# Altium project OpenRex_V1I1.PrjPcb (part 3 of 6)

## Sheet [12] - CPU - POWER.SchDoc
size A2; DocumentNumber: 12; SheetNumber: 12; SheetTotal: 31
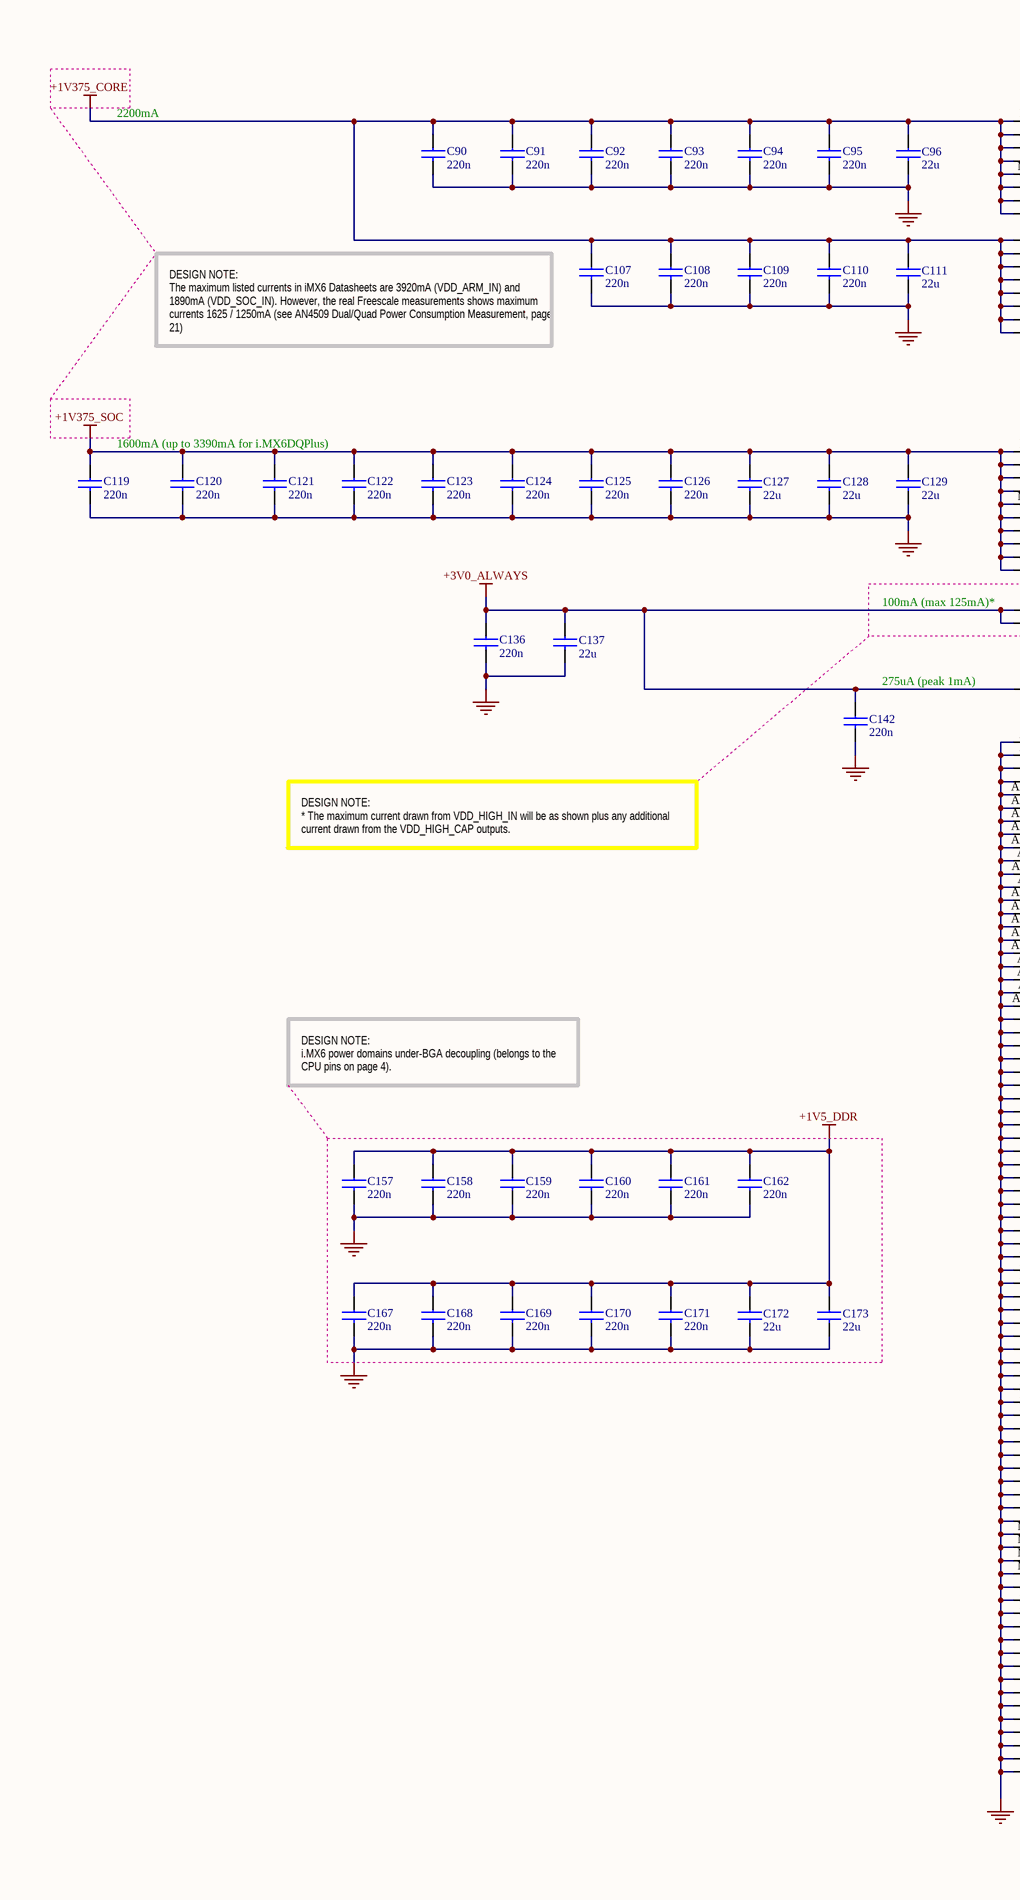
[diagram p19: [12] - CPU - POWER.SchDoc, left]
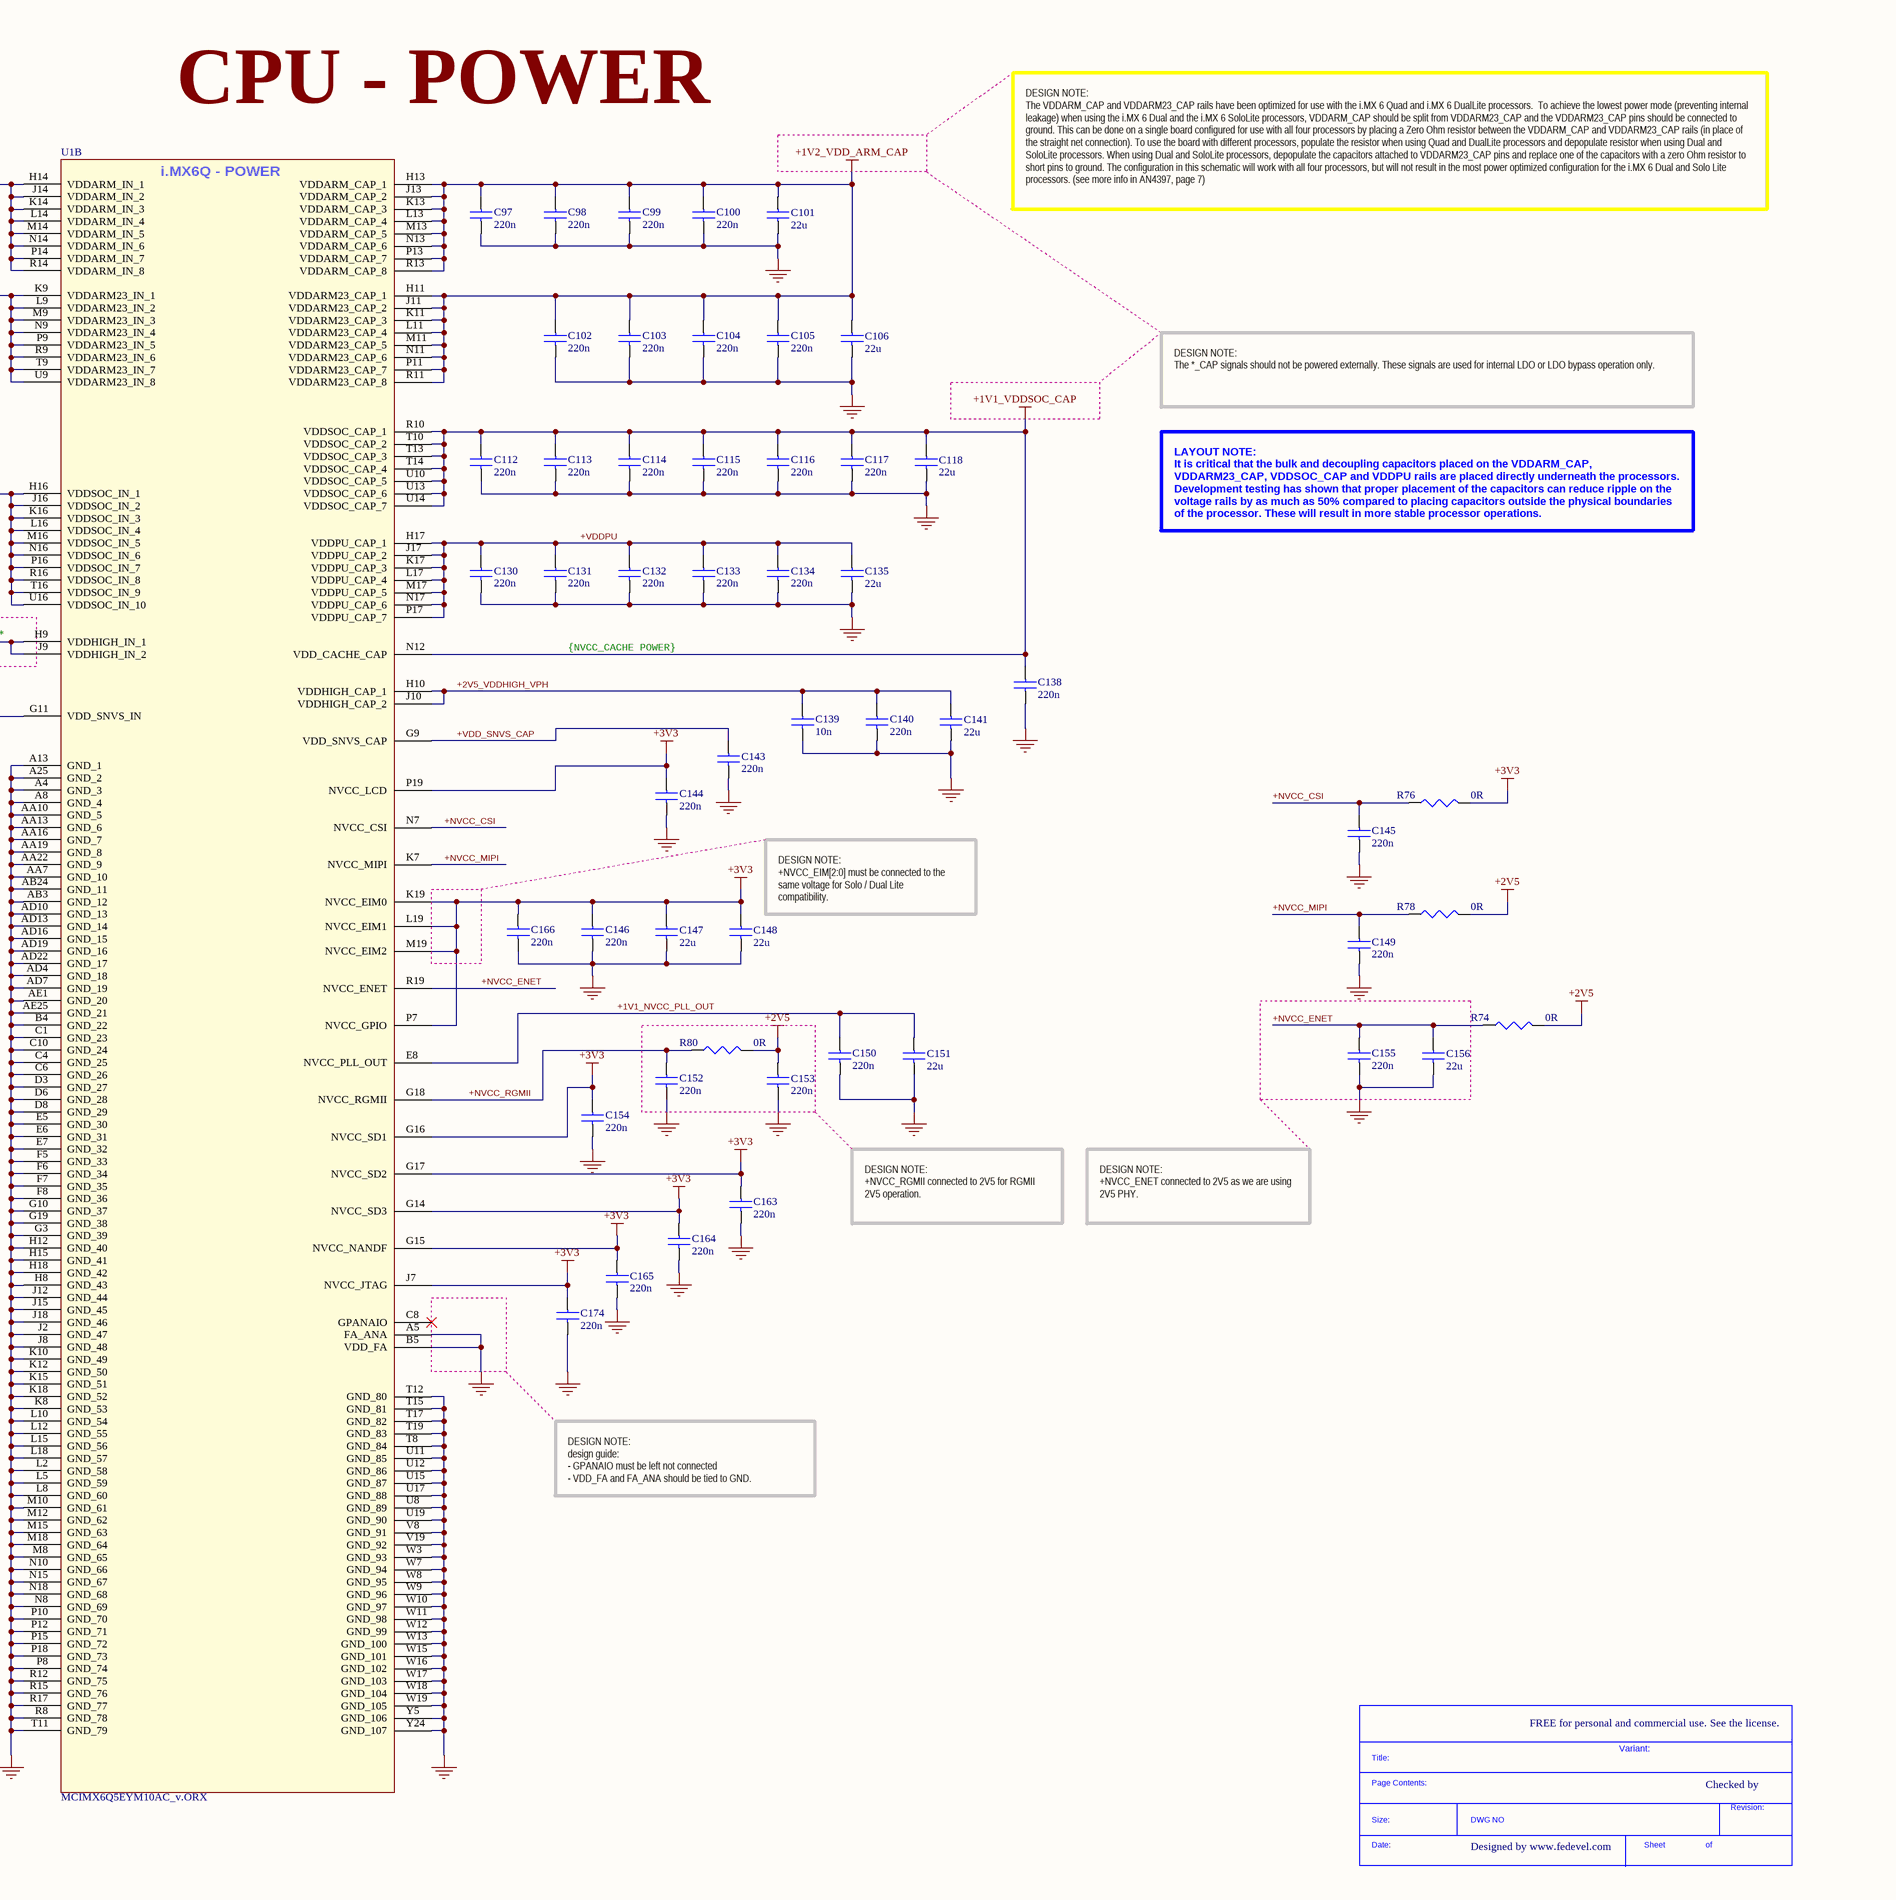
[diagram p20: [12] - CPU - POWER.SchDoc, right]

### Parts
(Parts that share a designator on the sheet are numbered #1, #2 ... from top to bottom, then left to right.)
*#13  SDTitleBlock  (value not drawn)  (graphical)
C90  220n  [C0201]
C91  220n  [C0201]
C92  220n  [C0201]
C93  220n  [C0201]
C94  220n  [C0201]
C95  220n  [C0201]
C96  22u  [C0603_small]
C97  220n  [C0201]
C98  220n  [C0201]
C99  220n  [C0201]
C100  220n  [C0201]
C101  22u  [C0603_small]
C102  220n  [C0201]
C103  220n  [C0201]
C104  220n  [C0201]
C105  220n  [C0201]
C106  22u  [C0603_small]
C107  220n  [C0201]
C108  220n  [C0201]
C109  220n  [C0201]
C110  220n  [C0201]
C111  22u  [C0603_small]
C112  220n  [C0201]
C113  220n  [C0201]
C114  220n  [C0201]
C115  220n  [C0201]
C116  220n  [C0201]
C117  220n  [C0201]
C118  22u  [C0603_small]
C119  220n  [C0201]
C120  220n  [C0201]
C121  220n  [C0201]
C122  220n  [C0201]
C123  220n  [C0201]
C124  220n  [C0201]
C125  220n  [C0201]
C126  220n  [C0201]
C127  22u  [C0603_small]
C128  22u  [C0603_small]
C129  22u  [C0603_small]
C130  220n  [C0201]
C131  220n  [C0201]
C132  220n  [C0201]
C133  220n  [C0201]
C134  220n  [C0201]
C135  22u  [C0603_small]
C136  220n  [C0201]
C137  22u  [C0603]
C138  220n  [C0201]
C139  10n  [C0201]
C140  220n  [C0201]
C141  22u  [C0603]
C142  220n  [C0201]
C143  220n  [C0201]
C144  220n  [C0201]
C145  220n  [C0201]
C146  220n  [C0201]
C147  22u  [C0603]
C148  22u  [C0603]
C149  220n  [C0201]
C150  220n  [C0201]
C151  22u  [C0603]
C152  220n  [C0201]
C153  220n  [C0402]
C154  220n  [C0201]
C155  220n  [C0201]
C156  22u  [C0603]
C157  220n  [C0201]
C158  220n  [C0201]
C159  220n  [C0201]
C160  220n  [C0201]
C161  220n  [C0201]
C162  220n  [C0201]
C163  220n  [C0201]
C164  220n  [C0201]
C165  220n  [C0201]
C166  220n  [C0201]
C167  220n  [C0201]
C168  220n  [C0201]
C169  220n  [C0201]
C170  220n  [C0201]
C171  220n  [C0201]
C172  22u  [C0603_small]
C173  22u  [C0603_small]
C174  220n  [C0201]
R74  0R  [R0402]
R76  0R  [R0402]
R78  0R  [R0402]
R80  0R  [R0402]
U1  MCIMX6Q5EYM10AC_v.ORX  [PBGA624]  (part B of 21)

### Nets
+1V1_VDDSOC_CAP: C112.1 C113.1 C114.1 C115.1 C116.1 C117.1 C118.1 C138.1 U1.N12(VDD_CACHE_CAP) U1.R10(VDDSOC_CAP_1) U1.T10(VDDSOC_CAP_2) U1.T13(VDDSOC_CAP_3) U1.T14(VDDSOC_CAP_4) U1.U10(VDDSOC_CAP_5) U1.U13(VDDSOC_CAP_6) U1.U14(VDDSOC_CAP_7)
+1V2_VDD_ARM_CAP: C97.1 C98.1 C99.1 C100.1 C101.1 C102.1 C103.1 C104.1 C105.1 C106.1 U1.H11(VDDARM23_CAP_1) U1.H13(VDDARM_CAP_1) U1.J11(VDDARM23_CAP_2) U1.J13(VDDARM_CAP_2) U1.K11(VDDARM23_CAP_3) U1.K13(VDDARM_CAP_3) U1.L11(VDDARM23_CAP_4) U1.L13(VDDARM_CAP_4) U1.M11(VDDARM23_CAP_5) U1.M13(VDDARM_CAP_5) U1.N11(VDDARM23_CAP_6) U1.N13(VDDARM_CAP_6) U1.P11(VDDARM23_CAP_7) U1.P13(VDDARM_CAP_7) U1.R11(VDDARM23_CAP_8) U1.R13(VDDARM_CAP_8)
+1V5_DDR: C157.1 C158.1 C159.1 C160.1 C161.1 C162.1 C167.1 C168.1 C169.1 C170.1 C171.1 C172.1 C173.1
+1V375_CORE: C90.1 C91.1 C92.1 C93.1 C94.1 C95.1 C96.1 C107.1 C108.1 C109.1 C110.1 C111.1 U1.H14(VDDARM_IN_1) U1.J14(VDDARM_IN_2) U1.K9(VDDARM23_IN_1) U1.K14(VDDARM_IN_3) U1.L9(VDDARM23_IN_2) U1.L14(VDDARM_IN_4) U1.M9(VDDARM23_IN_3) U1.M14(VDDARM_IN_5) U1.N9(VDDARM23_IN_4) U1.N14(VDDARM_IN_6) U1.P9(VDDARM23_IN_5) U1.P14(VDDARM_IN_7) U1.R9(VDDARM23_IN_6) U1.R14(VDDARM_IN_8) U1.T9(VDDARM23_IN_7) U1.U9(VDDARM23_IN_8)
+1V375_SOC: C119.1 C120.1 C121.1 C122.1 C123.1 C124.1 C125.1 C126.1 C127.1 C128.1 C129.1 U1.H16(VDDSOC_IN_1) U1.J16(VDDSOC_IN_2) U1.K16(VDDSOC_IN_3) U1.L16(VDDSOC_IN_4) U1.M16(VDDSOC_IN_5) U1.N16(VDDSOC_IN_6) U1.P16(VDDSOC_IN_7) U1.R16(VDDSOC_IN_8) U1.T16(VDDSOC_IN_9) U1.U16(VDDSOC_IN_10)
+2V5: C153.1 R74.2 R78.2 R80.2
+3V0_ALWAYS: C136.1 C137.1 C142.1 U1.G11(VDD_SNVS_IN) U1.H9(VDDHIGH_IN_1) U1.J9(VDDHIGH_IN_2)
+3V3: C144.1 C146.1 C147.1 C148.1 C154.1 C163.1 C164.1 C165.1 C166.1 C174.1 R76.2 U1.G14(NVCC_SD3) U1.G15(NVCC_NANDF) U1.G16(NVCC_SD1) U1.G17(NVCC_SD2) U1.J7(NVCC_JTAG) U1.K19(NVCC_EIM0) U1.L19(NVCC_EIM1) U1.M19(NVCC_EIM2) U1.P7(NVCC_GPIO) U1.P19(NVCC_LCD)
GND: C90.2 C91.2 C92.2 C93.2 C94.2 C95.2 C96.2 C97.2 C98.2 C99.2 C100.2 C101.2 C102.2 C103.2 C104.2 C105.2 C106.2 C107.2 C108.2 C109.2 C110.2 C111.2 C112.2 C113.2 C114.2 C115.2 C116.2 C117.2 C118.2 C119.2 C120.2 C121.2 C122.2 C123.2 C124.2 C125.2 C126.2 C127.2 C128.2 C129.2 C130.2 C131.2 C132.2 C133.2 C134.2 C135.2 C136.2 C137.2 C138.2 C139.2 C140.2 C141.2 C142.2 C143.2 C144.2 C145.2 C146.2 C147.2 C148.2 C149.2 C150.2 C151.2 C152.2 C153.2 C154.2 C155.2 C156.2 C157.2 C158.2 C159.2 C160.2 C161.2 C162.2 C163.2 C164.2 C165.2 C166.2 C167.2 C168.2 C169.2 C170.2 C171.2 C172.2 C173.2 C174.2 U1.A4(GND_3) U1.A5(FA_ANA) U1.A8(GND_4) U1.A13(GND_1) U1.A25(GND_2) U1.AA7(GND_10) U1.AA10(GND_5) U1.AA13(GND_6) U1.AA16(GND_7) U1.AA19(GND_8) U1.AA22(GND_9) U1.AB3(GND_12) U1.AB24(GND_11) U1.AD4(GND_18) U1.AD7(GND_19) U1.AD10(GND_13) U1.AD13(GND_14) U1.AD16(GND_15) U1.AD19(GND_16) U1.AD22(GND_17) U1.AE1(GND_20) U1.AE25(GND_21) U1.B4(GND_22) U1.B5(VDD_FA) U1.C1(GND_23) U1.C4(GND_25) U1.C6(GND_26) U1.C10(GND_24) U1.D3(GND_27) U1.D6(GND_28) U1.D8(GND_29) U1.E5(GND_30) U1.E6(GND_31) U1.E7(GND_32) U1.F5(GND_33) U1.F6(GND_34) U1.F7(GND_35) U1.F8(GND_36) U1.G3(GND_39) U1.G10(GND_37) U1.G19(GND_38) U1.H8(GND_43) U1.H12(GND_40) U1.H15(GND_41) U1.H18(GND_42) U1.J2(GND_47) U1.J8(GND_48) U1.J12(GND_44) U1.J15(GND_45) U1.J18(GND_46) U1.K8(GND_53) U1.K10(GND_49) U1.K12(GND_50) U1.K15(GND_51) U1.K18(GND_52) U1.L2(GND_58) U1.L5(GND_59) U1.L8(GND_60) U1.L10(GND_54) U1.L12(GND_55) U1.L15(GND_56) U1.L18(GND_57) U1.M8(GND_65) U1.M10(GND_61) U1.M12(GND_62) U1.M15(GND_63) U1.M18(GND_64) U1.N8(GND_69) U1.N10(GND_66) U1.N15(GND_67) U1.N18(GND_68) U1.P8(GND_74) U1.P10(GND_70) U1.P12(GND_71) U1.P15(GND_72) U1.P18(GND_73) U1.R8(GND_78) U1.R12(GND_75) U1.R15(GND_76) U1.R17(GND_77) U1.T8(GND_84) U1.T11(GND_79) U1.T12(GND_80) U1.T15(GND_81) U1.T17(GND_82) U1.T19(GND_83) U1.U8(GND_89) U1.U11(GND_85) U1.U12(GND_86) U1.U15(GND_87) U1.U17(GND_88) U1.U19(GND_90) U1.V8(GND_91) U1.V19(GND_92) U1.W3(GND_93) U1.W7(GND_94) U1.W8(GND_95) U1.W9(GND_96) U1.W10(GND_97) U1.W11(GND_98) U1.W12(GND_99) U1.W13(GND_100) U1.W15(GND_101) U1.W16(GND_102) U1.W17(GND_103) U1.W18(GND_104) U1.W19(GND_105) U1.Y5(GND_106) U1.Y24(GND_107)
+1V1_NVCC_PLL_OUT: C150.1 C151.1 U1.E8(NVCC_PLL_OUT)
+2V5_VDDHIGH_VPH: C139.1 C140.1 C141.1 U1.H10(VDDHIGH_CAP_1) U1.J10(VDDHIGH_CAP_2)
+NVCC_CSI: C145.1 R76.1 U1.N7(NVCC_CSI)
+NVCC_ENET: C155.1 C156.1 R74.1 U1.R19(NVCC_ENET)
+NVCC_MIPI: C149.1 R78.1 U1.K7(NVCC_MIPI)
+NVCC_RGMII: C152.1 R80.1 U1.G18(NVCC_RGMII)
+VDD_SNVS_CAP: C143.1 U1.G9(VDD_SNVS_CAP)
+VDDPU: C130.1 C131.1 C132.1 C133.1 C134.1 C135.1 U1.H17(VDDPU_CAP_1) U1.J17(VDDPU_CAP_2) U1.K17(VDDPU_CAP_3) U1.L17(VDDPU_CAP_4) U1.M17(VDDPU_CAP_5) U1.N17(VDDPU_CAP_6) U1.P17(VDDPU_CAP_7)

Not connected (* = marked no-connect by the designer): U1 C8(GPANAIO)*

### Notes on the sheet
- CPU - POWER
- 2200mA
- DESIGN NOTE:
  The VDDARM_CAP and VDDARM23_CAP rails have been optimized for use with the i.MX 6 Quad and i.MX 6 DualLite processors.  To achieve the lowest power mode (preventing internal leakage) when using the i.MX 6 Dual and the i.MX 6 SoloLite processors, VDDARM_CAP should be split from VDDARM23_CAP and the VDDARM23_CAP pins should be connected to ground. This can be done on a single board configured for use with all four processors by placing a Zero Ohm resistor between the VDDARM_CAP and VDDARM23_CAP rails (in place of the straight net connection). To use the board with different processors, populate the resistor when using Quad and DualLite processors and depopulate resistor when using Dual and SoloLite processors. When using Dual and SoloLite processors, depopulate the capacitors attached to VDDARM23_CAP pins and replace one of the capacitors with a zero Ohm resistor to short pins to ground. The configuration in this schematic will work with all four processors, but will not result in the most power optimized configuration for the i.MX 6 Dual and Solo Lite processors. (see more info in AN4397, page 7)
- (near C107) DESIGN NOTE:
  The maximum listed currents in iMX6 Datasheets are 3920mA (VDD_ARM_IN) and 1890mA (VDD_SOC_IN). However, the real Freescale measurements shows maximum currents 1625 / 1250mA (see AN4509 Dual/Quad Power Consumption Measurement, page 21)
- DESIGN NOTE:
  The *_CAP signals should not be powered externally. These signals are used for internal LDO or LDO bypass operation only.
- 1600mA (up to 3390mA for i.MX6DQPlus)
- LAYOUT NOTE:
  It is critical that the bulk and decoupling capacitors placed on the VDDARM_CAP, VDDARM23_CAP, VDDSOC_CAP and VDDPU rails are placed directly underneath the processors. Development testing has shown that proper placement of the capacitors can reduce ripple on the voltage rails by as much as 50% compared to placing capacitors outside the physical boundaries of the processor. These will result in more stable processor operations.
- 100mA (max 125mA)*
- {NVCC_CACHE POWER}
- (near C142) 275uA (peak 1mA)
- DESIGN NOTE:
  * The maximum current drawn from VDD_HIGH_IN will be as shown plus any additional current drawn from the VDD_HIGH_CAP outputs.
- (near C148) DESIGN NOTE:
  +NVCC_EIM[2:0] must be connected to the same voltage for Solo / Dual Lite compatibility.
- DESIGN NOTE:
  i.MX6 power domains under-BGA decoupling (belongs to the CPU pins on page 4).
- DESIGN NOTE:
  +NVCC_RGMII connected to 2V5 for RGMII 2V5 operation.
- DESIGN NOTE:
  +NVCC_ENET connected to 2V5 as we are using 2V5 PHY.
- DESIGN NOTE:
  design guide:
  - GPANAIO must be left not connected
  - VDD_FA and FA_ANA should be tied to GND.
- FREE for personal and commercial use. See the license.
- Variant:
- Checked by
- Designed by www.fedevel.com

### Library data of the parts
C90-C95 C97-C100 C102-C105 C107-C110 C112-C117 C119-C126 C130-C134 C136 C138 C140 C142-C146 C149 C150 C152 C154 C155 C157-C171 C174 = C0603X5R0J224M030BB: CAP CER 0.22UF 6.3V 20% X5R 0201; Manufacturer: TDK Corporation; Capacitance: 0.22µF; .Checked PCB: MM
C96 C101 C106 C111 C118 C127-C129 C135 C172 C173 = GRM188R60G226MEA0L_small: CAP CER 22UF 4V 20% X5R 0603; Manufacturer: Murata Electronics North America; Capacitance: 22µF; .Checked PCB: MM; .Checked SCH: RF, used by MM
C137 C141 C147 C148 C151 C156 = C1608X5R0J226M080AC: CAP CER 22UF 6.3V 20% X5R 0603; Manufacturer: TDK Corporation; Capacitance: 22µF; .Creator: MM
C139 = C0603X5R1C103K030BA: CAP CER .01UF 16V 10% X5R 0201; Manufacturer: TDK Corporation; Capacitance: 10000pF; .Creator: MM
C153 = C1005X5R1E224M: CAP CER .22UF 25V X5R 20% 0402; Manufacturer: TDK Corporation; Capacitance: 0.22µF; Value: 220nF; .Checked PCB: used
R74 R76 R78 R80 = RC0402JR-070RL: RES 0.0 OHM 1/16W 0402 SMD; Manufacturer: Yageo; Resistance (Ohms): 0.0; Power (Watts): 0.063W, 1/16W; Tolerance: Jumper; .Checked PCB: used
U1 = MCIMX6Q5EYM10AC_v.ORX: IC MCU 32BIT ARM QUAD 624FCBGA; Manufacturer: Freescale Semiconductor; Core Processor: ARM® Cortex™-A9; Core Size: 32-Bit Quad-Core; Speed: 1.0GHz; Connectivity: CAN, EBI/EMI, ESAI, Ethernet, GPMI, I2C, MMC/SD, PCI, SATA, SPI, UART, USB, USB OTG; Peripherals: DMA, HDMI, I2S/SSI/AC97, MIPI CSI, MIMI DSI, MIPI HIS, PWM, WDT; Number of I /O: 224; Program Memory Type: External Program Memory; RAM Size: 256K x 8; Voltage - Supply (Vcc/Vdd): 0.925 V ~ 1.5 V; Oscillator Type: Internal; .Creator: MM; .Checked PCB: MM, checked by RF

## Sheet [18] - PCIE MINI.SchDoc
size A2; DocumentNumber: 18; SheetNumber: 18; SheetTotal: 31
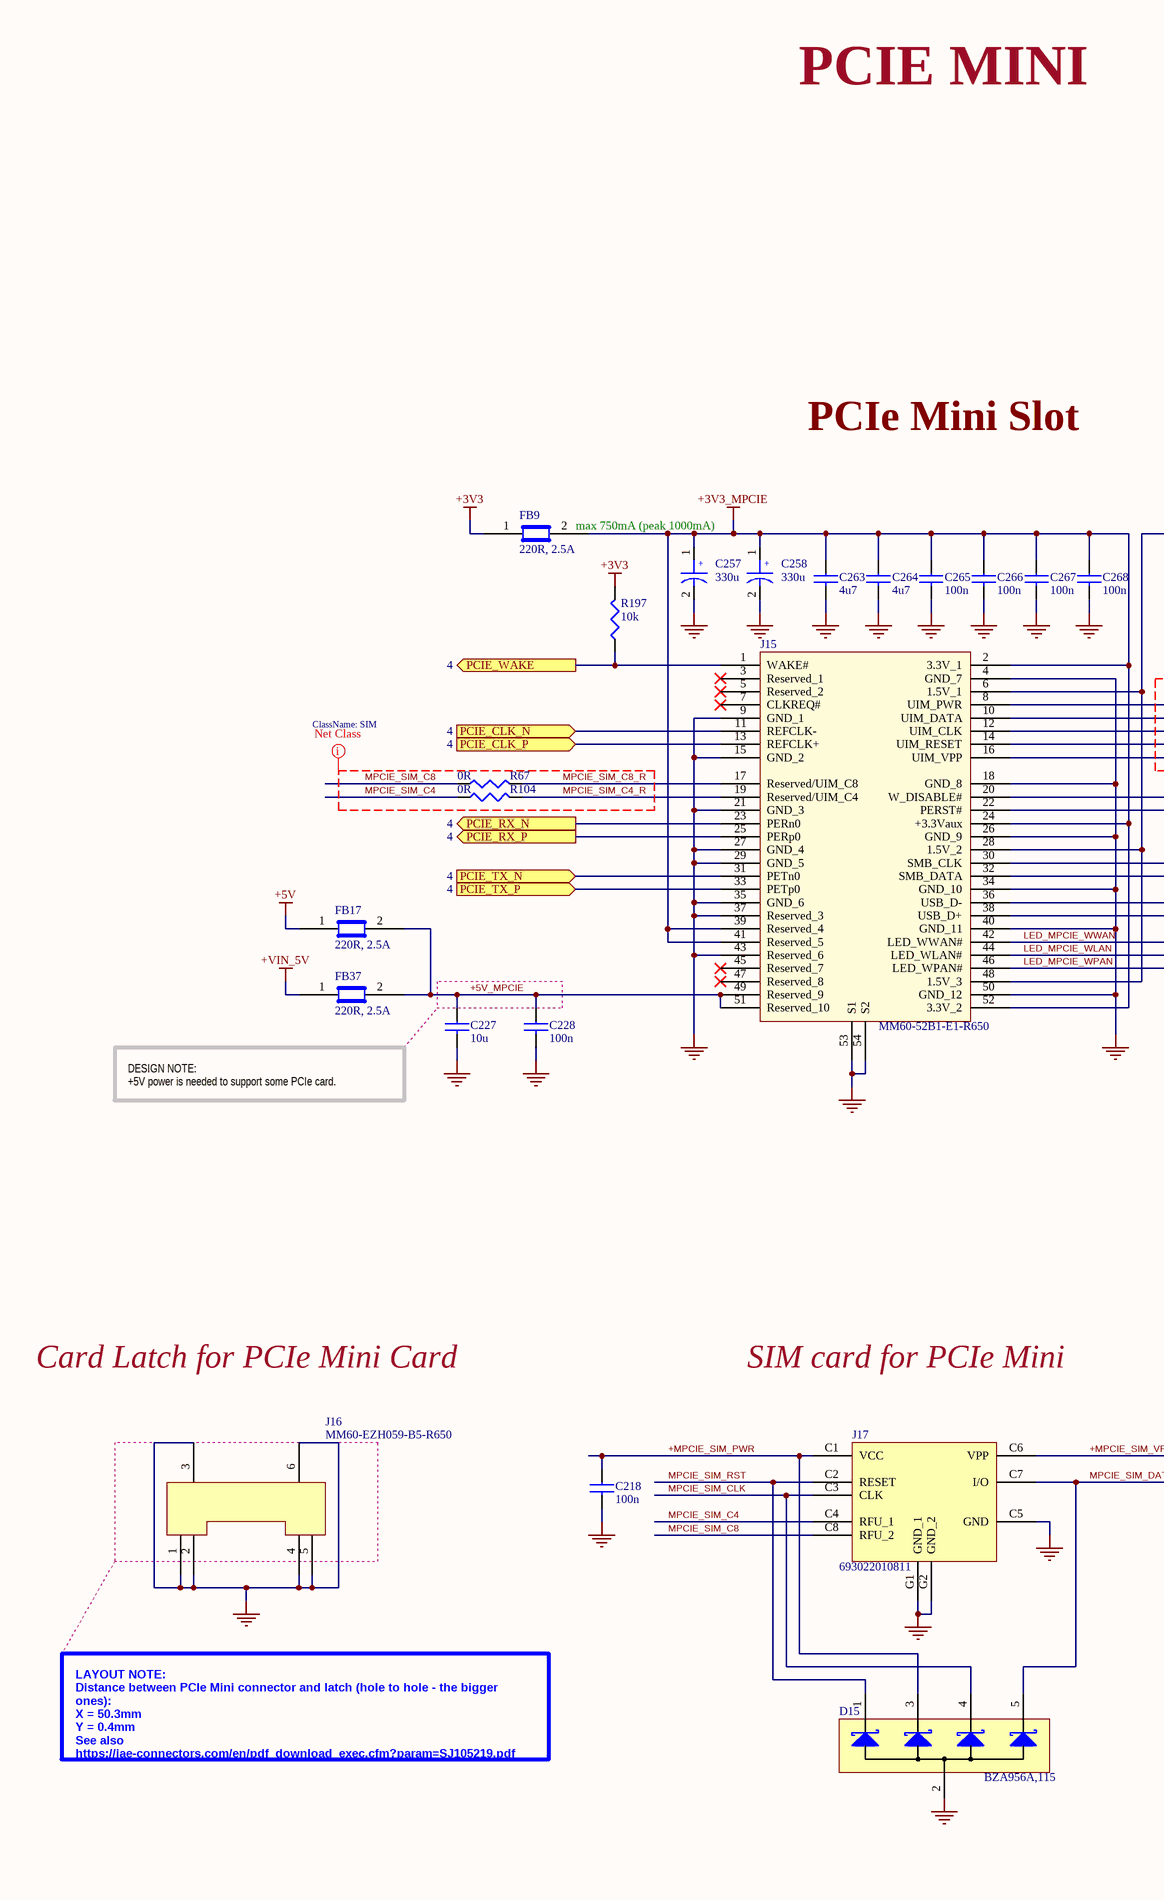
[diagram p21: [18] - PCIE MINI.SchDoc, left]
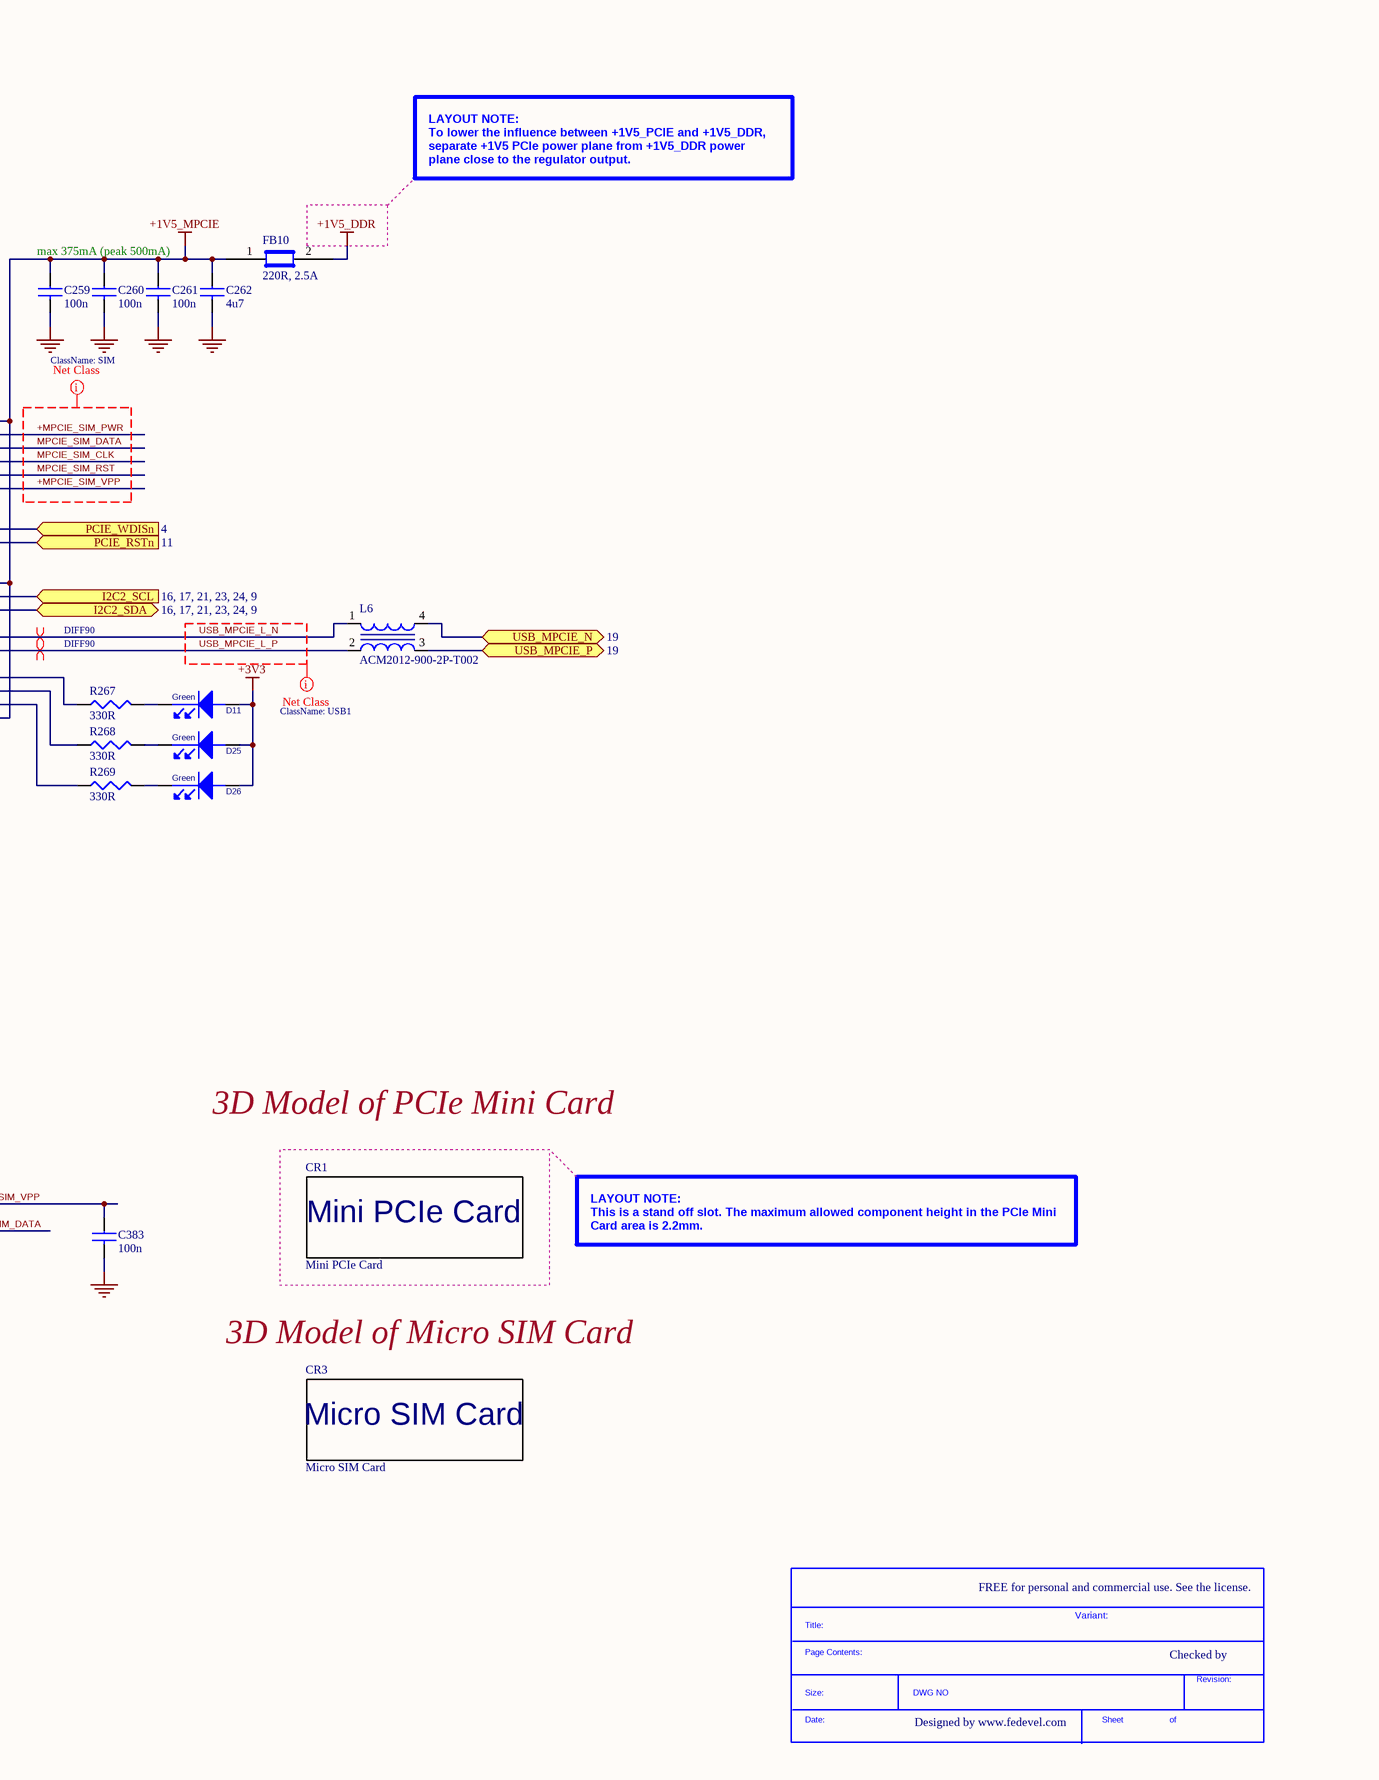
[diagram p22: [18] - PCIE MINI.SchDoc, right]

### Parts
(Parts that share a designator on the sheet are numbered #1, #2 ... from top to bottom, then left to right.)
*#14  SDTitleBlock  (value not drawn)  (graphical)
C218  100n  [C0402]
C227  10u  [C0603]
C228  100n  [C0402]
C257  330u  [C2917]
C258  330u  [C2917]
C259  100n  [C0402]
C260  100n  [C0402]
C261  100n  [C0402]
C262  4u7  [C0402]
C263  4u7  [C0402]
C264  4u7  [C0402]
C265  100n  [C0402]
C266  100n  [C0402]
C267  100n  [C0402]
C268  100n  [C0402]
C383  100n  [C0402]
CR1  Mini PCIe Card  [Mini_PCIe_full card]  (no BOM)
CR3  Micro SIM Card  [Micro_Sim_card]  (no BOM)
D11  Green  [LED_0603]
D15  BZA956A,115  [SOT665]
D25  Green  [LED_0603]
D26  Green  [LED_0603]
FB9  220R, 2.5A  [C0603]
FB10  220R, 2.5A  [C0603]
FB17  220R, 2.5A  [C0603]
FB37  220R, 2.5A  [C0603]
J15  MM60-52B1-E1-R650  [MINI_PCIE_52PIN_CARD_CON]
J16  MM60-EZH059-B5-R650  [MINI_PCIE_52PIN_CARD_LATCH]
J17  693022010811  [SIM_MICRO_HINGED]
L6  ACM2012-900-2P-T002  [ACM2012]
R67  0R  [R0402]
R104  0R  [R0402]
R197  10k  [R0402]
R267  330R  [R0402]
R268  330R  [R0402]
R269  330R  [R0402]

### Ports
I2C2_SCL (see 16, 17, 21, 23, 24, 9), I2C2_SDA (bidir, see 16, 17, 21, 23, 24, 9), PCIE_CLK_N (in, see 4), PCIE_CLK_P (in, see 4), PCIE_RSTn (in, see 11), PCIE_RX_N (out, see 4), PCIE_RX_P (out, see 4), PCIE_TX_N (in, see 4), PCIE_TX_P (in, see 4), PCIE_WAKE (out, see 4), PCIE_WDISn (in, see 4), USB_MPCIE_N (bidir, see 19), USB_MPCIE_P (bidir, see 19)

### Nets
+1V5_DDR: FB10.2
+1V5_MPCIE: C259.1 C260.1 C261.1 C262.1 FB10.1 J15.6(1.5V_1) J15.28(1.5V_2) J15.48(1.5V_3)
+3V3: D11.2(ANODE) D25.2(ANODE) D26.2(ANODE) FB9.1 R197.2
+3V3_MPCIE: C257.1 C258.1 C263.1 C264.1 C265.1 C266.1 C267.1 C268.1 FB9.2 J15.2(3.3V_1) J15.24(+3.3Vaux) J15.39(Reserved_4) J15.41(Reserved_5) J15.52(3.3V_2)
+5V: FB17.1
+VIN_5V: FB37.1
GND: C218.2 C227.2 C228.2 C257.2 C258.2 C259.2 C260.2 C261.2 C262.2 C263.2 C264.2 C265.2 C266.2 C267.2 C268.2 C383.2 D15.2 J15.4(GND_7) J15.9(GND_1) J15.15(GND_2) J15.18(GND_8) J15.21(GND_3) J15.26(GND_9) J15.27(GND_4) J15.29(GND_5) J15.34(GND_10) J15.35(GND_6) J15.37(Reserved_3) J15.40(GND_11) J15.43(Reserved_6) J15.50(GND_12) J15.53(S1) J15.54(S2) J16.1 J16.2 J16.3 J16.4 J16.5 J16.6 J17.C5(GND) J17.G1(GND_1) J17.G2(GND_2)
+5V_MPCIE: C227.1 C228.1 FB17.2 FB37.2 J15.49(Reserved_9) J15.51(Reserved_10)
+MPCIE_SIM_PWR: C218.1 D15.3 J15.8(UIM_PWR) J17.C1(VCC)
+MPCIE_SIM_VPP: C383.1 J15.16(UIM_VPP) J17.C6(VPP)
I2C2_SCL: J15.30(SMB_CLK) ; port I2C2_SCL
I2C2_SDA: J15.32(SMB_DATA) ; port I2C2_SDA
LED_MPCIE_WLAN: J15.44(LED_WLAN#) R268.1
LED_MPCIE_WPAN: J15.46(LED_WPAN#) R269.1
LED_MPCIE_WWAN: J15.42(LED_WWAN#) R267.1
MPCIE_SIM_C4: J17.C4(RFU_1) R104.1
MPCIE_SIM_C4_R: J15.19(Reserved/UIM_C4) R104.2
MPCIE_SIM_C8: J17.C8(RFU_2) R67.1
MPCIE_SIM_C8_R: J15.17(Reserved/UIM_C8) R67.2
MPCIE_SIM_CLK: D15.4 J15.12(UIM_CLK) J17.C3(CLK)
MPCIE_SIM_DATA: D15.5 J15.10(UIM_DATA) J17.C7(I/O)
MPCIE_SIM_RST: D15.1 J15.14(UIM_RESET) J17.C2(RESET)
PCIE_CLK_N: J15.11(REFCLK-) ; port PCIE_CLK_N
PCIE_CLK_P: J15.13(REFCLK+) ; port PCIE_CLK_P
PCIE_RSTn: J15.22(PERST#) ; port PCIE_RSTn
PCIE_RX_N: J15.23(PERn0) ; port PCIE_RX_N
PCIE_RX_P: J15.25(PERp0) ; port PCIE_RX_P
PCIE_TX_N: J15.31(PETn0) ; port PCIE_TX_N
PCIE_TX_P: J15.33(PETp0) ; port PCIE_TX_P
PCIE_WAKE: J15.1(WAKE#) R197.1 ; port PCIE_WAKE
PCIE_WDISn: J15.20(W_DISABLE#) ; port PCIE_WDISn
USB_MPCIE_L_N: J15.36(USB_D-) L6.1
USB_MPCIE_L_P: J15.38(USB_D+) L6.2
USB_MPCIE_N: L6.4 ; port USB_MPCIE_N
USB_MPCIE_P: L6.3 ; port USB_MPCIE_P
NetD11_1: D11.1(cathode) R267.2
NetD25_1: D25.1(cathode) R268.2
NetD26_1: D26.1(cathode) R269.2

Not connected (* = marked no-connect by the designer): J15 3(Reserved_1)* 5(Reserved_2)* 7(CLKREQ#)* 45(Reserved_7)* 47(Reserved_8)*

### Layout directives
differential pair; net class DIFF90: USB_MPCIE_L_N, USB_MPCIE_L_P
net class USB1: USB_MPCIE_L_N, USB_MPCIE_L_P
net class SIM: +MPCIE_SIM_PWR, +MPCIE_SIM_VPP, MPCIE_SIM_C4, MPCIE_SIM_C4_R, MPCIE_SIM_C8, MPCIE_SIM_C8_R, MPCIE_SIM_CLK, MPCIE_SIM_DATA, MPCIE_SIM_RST

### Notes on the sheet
- PCIE MINI
- PCIe Mini Slot
- LAYOUT NOTE:
  To lower the influence between +1V5_PCIE and +1V5_DDR, separate +1V5 PCIe power plane from +1V5_DDR power plane close to the regulator output.
- max 750mA (peak 1000mA)
- max 375mA (peak 500mA)
- DESIGN NOTE:
  +5V power is needed to support some PCIe card.
- Card Latch for PCIe Mini Card
- SIM card for PCIe Mini
- 3D Model of PCIe Mini Card
- LAYOUT NOTE:
  This is a stand off slot. The maximum allowed component height in the PCIe Mini Card area is 2.2mm.
- 3D Model of Micro SIM Card
- LAYOUT NOTE:
  Distance between PCIe Mini connector and latch (hole to hole - the bigger ones):
  X = 50.3mm
  Y = 0.4mm
  See also https://jae-connectors.com/en/pdf_download_exec.cfm?param=SJ105219.pdf
- FREE for personal and commercial use. See the license.
- Variant:
- Checked by
- Designed by www.fedevel.com

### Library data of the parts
C218 C228 C259-C261 C265-C268 C383 = C1005X5R1H104K: CAP CER .10UF 50V X5R 10% 0402; Manufacturer: TDK Corporation; Capacitance: 0.1µF; Value: 100nF; .Checked PCB: used
C227 = C1608X5R0J106M: CAP CER 10UF 6.3V X5R 20% 0603; Manufacturer: TDK Corporation; Capacitance: 10µF; Value: 10µF; .Checked PCB: used
C257 C258 = T520D337M006ATE045: CAP TANT 330UF 6.3V 20% 2917; Manufacturer: Kemet; Manufacturer Size Code: D; Capacitance: 330µF; ESR (Equivalent Series Resistance): 45 mOhm; Type: Molded; .Creator: MM; .Checked PCB: used
C262-C264 = C1005X5R1A475M: CAP CER 4.7UF 10V 20% X5R 0402; Manufacturer: TDK Corporation; Capacitance: 4.7µF; .Checked PCB: used
CR1 = Card_Mini_PCIe: Card MIni PCIe; .Creator: MM
CR3 = Card_Micro_SIM: Card Micro SIM; .Creator: MM
D11 D25 D26 = LG L29K-G2J1-24-Z: LED SMARTLED GREEN 570NM 0603; Manufacturer: OSRAM Opto Semiconductors Inc; .Checked PCB: used; Current - Test: 2mA; Voltage - Forward (Vf) Typ: 1.7V; Luminous Flux @ Current - Test: 12 mlm; Millicandela Rating: 3.92mcd; Wavelength - Peak: 572nm; Lens Type: Diffused; Lens Style/Size: Rectangle with Flat Top, 1.3mm x 0.8mm; Viewing Angle: 160°; Regulator Topology: Positive Fixed; Voltage - Output: 2.5V; Voltage - Input: 2.6 V ~ 6 V; Voltage - Dropout (Typical): 0.16V @ 500mA; Number of Regulators: 1; Current - Output: 500mA; Current - Limit (Min): 600mA
D15 = BZA956A,115: TVS ZENER QUAD 5.6V SOT665; Manufacturer: NXP Semiconductors; Voltage - Reverse Standoff (Typ): 3V; Voltage - Breakdown: 5.32V; Power (Watts): 16W; Polarization: 4 Channel Array - Unidirectional; .Creator: MM; .Checked PCB: used
FB9 FB10 FB17 FB37 = BLM18SG221TN1D: FERRITE CHIP 220 OHM 2500MA 0603; Manufacturer: Murata Electronics North America; Impedance @ Frequency: 220 Ohm @ 100MHz; DC Resistance (DCR): 40 mOhm Max; Filter Type: Differential Mode - Single; Number of Lines: 1; .Checked PCB: used
J15 = MM60-52B1-E1-R650: CONN MINI EXPRESS CARD 52POS SMD; Manufacturer: JAE Electronics; Card Type: PCI Express Mini Card; Gender: Female; Number of Positions: 52; Card Thickness: 0.039" (1.00mm); Pitch: 0.031" (0.80mm); Material - Insulation: Thermoplastic; Read Out: Dual; .Creator: MM; .Checked PCB: used
J16 = MM60-EZH059-B5-R650: CONN MINI EXPRESS CARD LATCH SMD; Manufacturer: JAE Electronics; For Use With/Related Products: PCI Express Mini Card; .Creator: MM; .Checked PCB: used
J17 = 693022010811: CONN SMART CARD; Manufacturer: Wurth Electronics Inc; Card Type: Micro SIM; Number of Positions: 8; Connector Type: Connector and Ejector; Insertion, Removal Method: Hinged Lid; .Creator: MM
L6 = ACM2012-900-2P-T002: CHOKE COMM MODE 90 OHM .4A SMD; Manufacturer: TDK Corporation; Filter Type: Data, Signal Line; Number of Lines: 2; Current: 400mA; DC Resistance (DCR): 190 mOhm Max; Impedance: 90 Ohm; Resistance (Ohms): 8.2K; Power (Watts): 0.063W, 1/16W; Temperature Coefficient: ±100ppm/°C; Tolerance: ±1%; .Checked PCB: used
R67 R104 = RC0402JR-070RL: as R74 on sheet [12] - CPU - POWER
R197 = RC0402FR-0710KL: RES 10.0K OHM 1/16W 1% 0402 SMD; Manufacturer: Yageo; Power (Watts): 0.063W, 1/16W; .Checked PCB: used; Temperature Coefficient: ±100ppm/°C
R267-R269 = CRCW0402330RFKED: RES 330 OHM 1/16W 1% 0402 SMD; Manufacturer: Vishay Dale; Resistance (Ohms): 330; Power (Watts): 0.063W, 1/16W; Temperature Coefficient: ±100ppm/°C; .Checked PCB: used

## Sheet [13] - CPU - UNUSED.SchDoc
size A2; DocumentNumber: 13; SheetNumber: 13; SheetTotal: 31
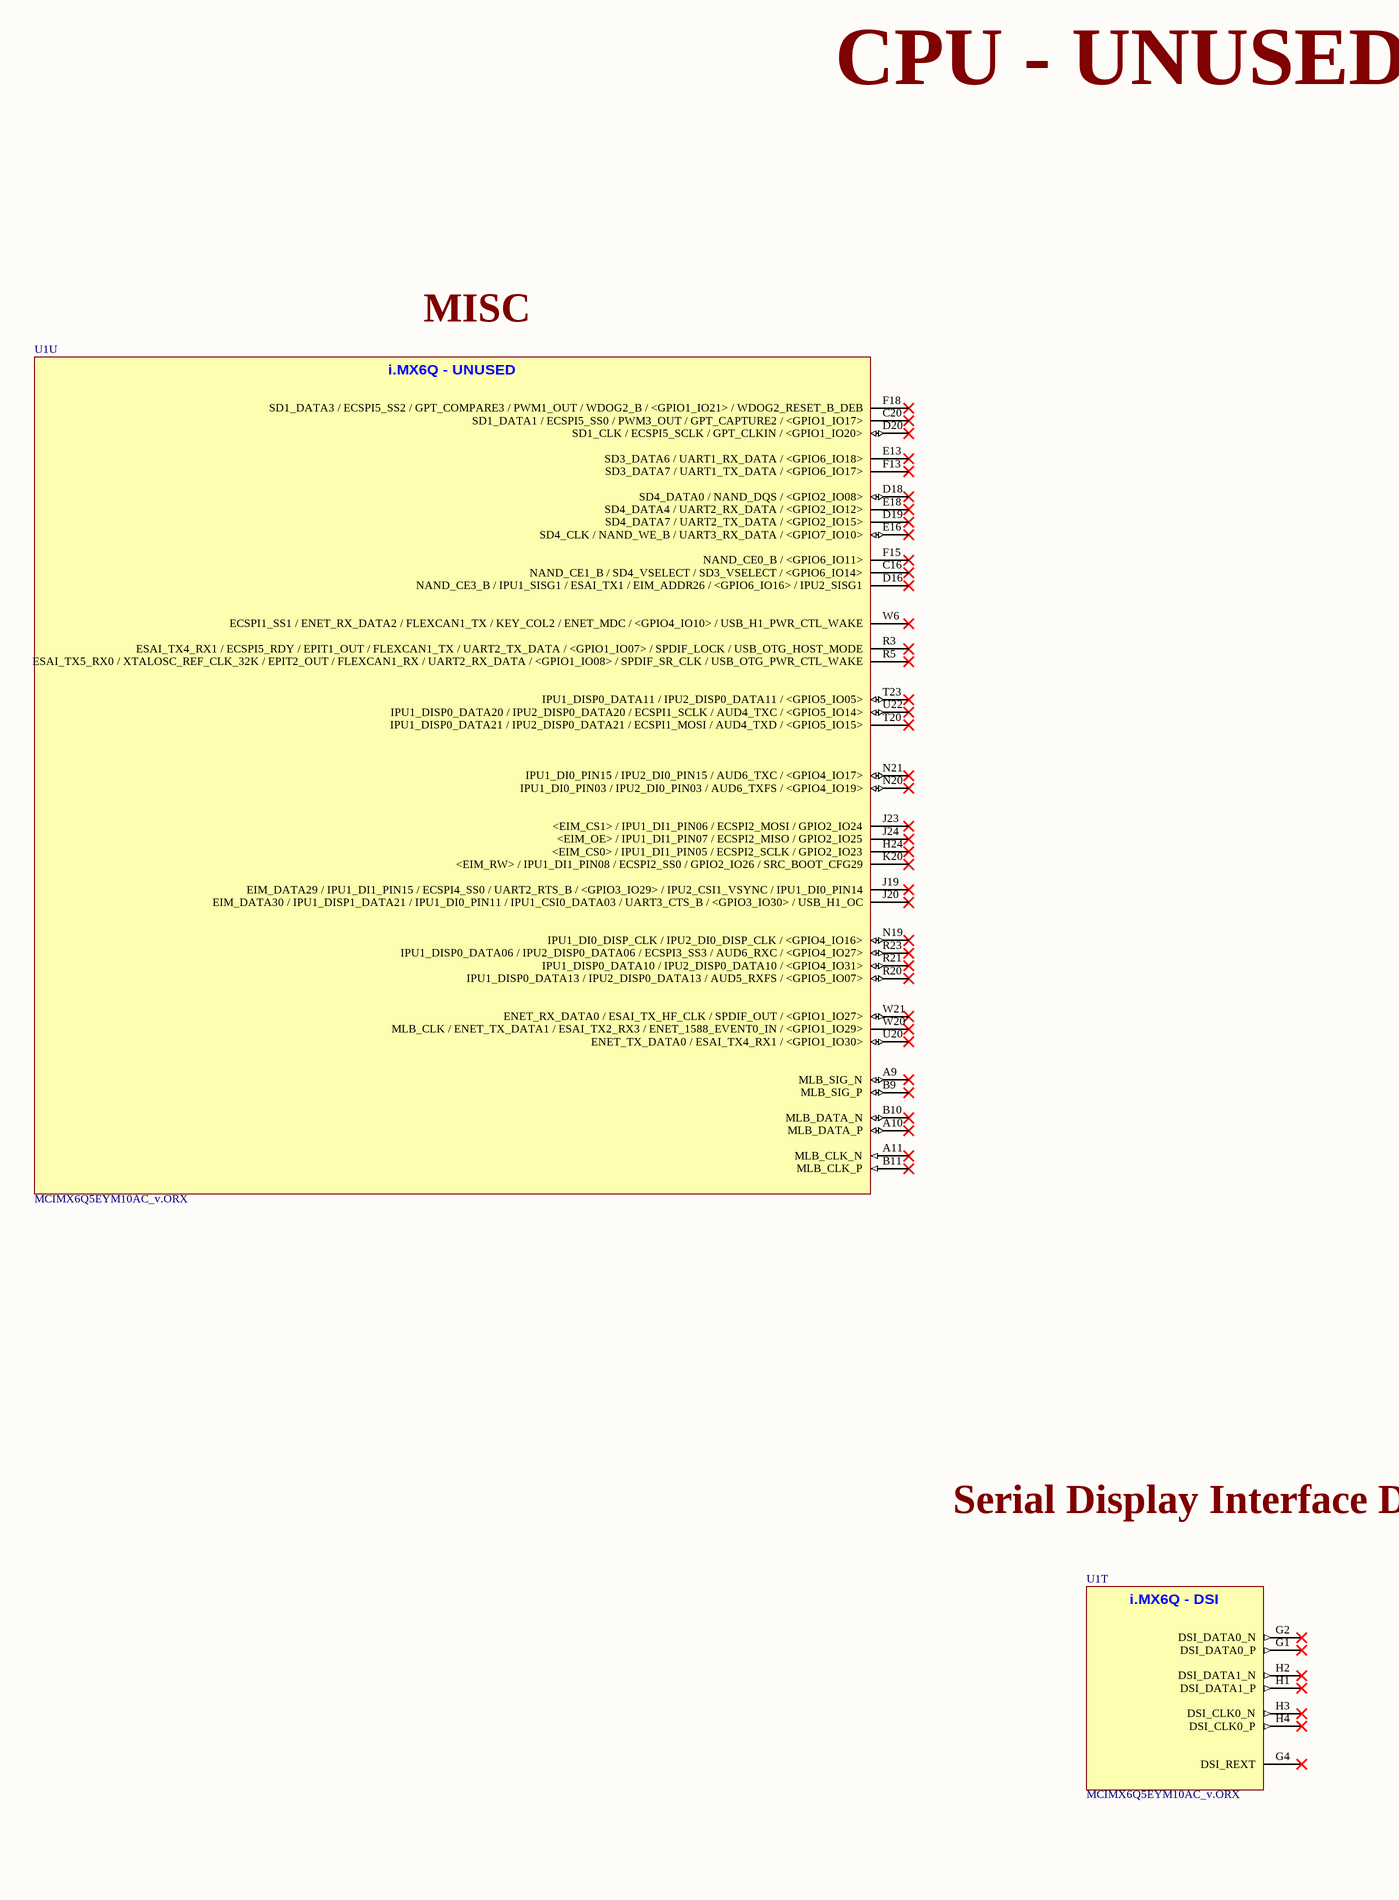
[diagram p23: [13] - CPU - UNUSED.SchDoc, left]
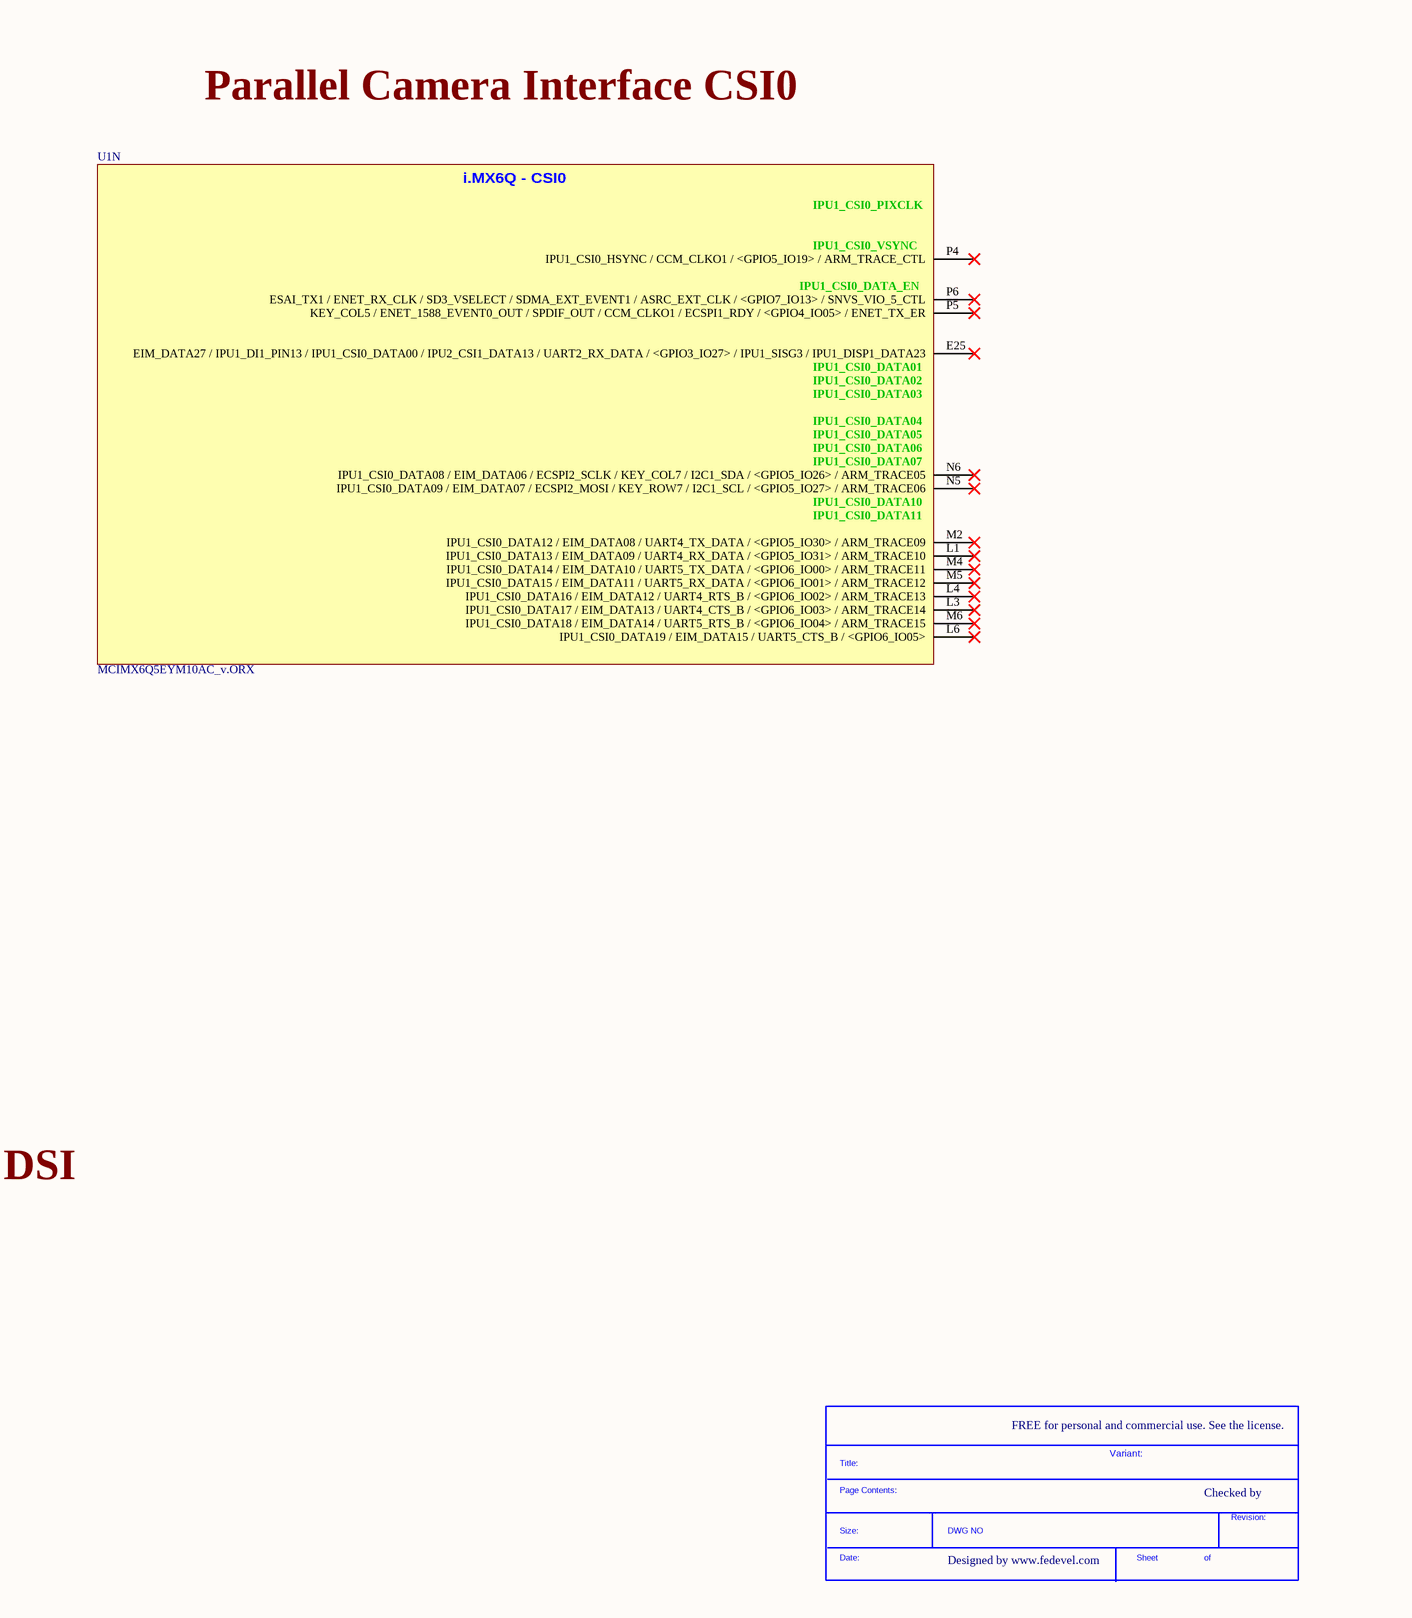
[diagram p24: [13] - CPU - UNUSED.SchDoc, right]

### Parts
(Parts that share a designator on the sheet are numbered #1, #2 ... from top to bottom, then left to right.)
*#15  SDTitleBlock  (value not drawn)  (graphical)
U1  MCIMX6Q5EYM10AC_v.ORX  [PBGA624]  (parts N,T,U of 21)

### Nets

Not connected (* = marked no-connect by the designer): U1 A9(MLB_SIG_N)* A10(MLB_DATA_P)* A11(MLB_CLK_N)* B9(MLB_SIG_P)* B10(MLB_DATA_N)* B11(MLB_CLK_P)* C16(NAND_CE1_B_/_SD4_VSELECT_/_SD3_VSELECT_/_<GPIO6_IO14>)* C20(SD1_DATA1_/_ECSPI5_SS0_/_PWM3_OUT_/_GPT_CAPTURE2_/_<GPIO1_IO17>)* D16(NAND_CE3_B_/_IPU1_SISG1_/_ESAI_TX1_/_EIM_ADDR26_/_<GPIO6_IO16>_/_IPU2_SISG1)* D18(SD4_DATA0_/_NAND_DQS_/_<GPIO2_IO08>)* D19(SD4_DATA7_/_UART2_TX_DATA_/_<GPIO2_IO15>)* D20(SD1_CLK_/_ECSPI5_SCLK_/_GPT_CLKIN_/_<GPIO1_IO20>)* E13(SD3_DATA6_/_UART1_RX_DATA_/_<GPIO6_IO18>)* E16(SD4_CLK_/_NAND_WE_B_/_UART3_RX_DATA_/_<GPIO7_IO10>)* E18(SD4_DATA4_/_UART2_RX_DATA_/_<GPIO2_IO12>)* E25(EIM_DATA27_/_IPU1_DI1_PIN13_/_IPU1_CSI0_DATA00_/_IPU2_CSI1_DATA13_/_UART2_RX_DATA_/_<GPIO3_IO27>_/_IPU1_SISG3_/_IPU1_DISP1_DATA23)* F13(SD3_DATA7_/_UART1_TX_DATA_/_<GPIO6_IO17>)* F15(NAND_CE0_B_/_<GPIO6_IO11>)* F18(SD1_DATA3_/_ECSPI5_SS2_/_GPT_COMPARE3_/_PWM1_OUT_/_WDOG2_B_/_<GPIO1_IO21>_/_WDOG2_RESET_B_DEB)* G1(DSI_DATA0_P)* G2(DSI_DATA0_N)* G4(DSI_REXT)* H1(DSI_DATA1_P)* H2(DSI_DATA1_N)* H3(DSI_CLK0_N)* H4(DSI_CLK0_P)* H24(<EIM_CS0>_/_IPU1_DI1_PIN05_/_ECSPI2_SCLK_/_GPIO2_IO23)* J19(EIM_DATA29_/_IPU1_DI1_PIN15_/_ECSPI4_SS0_/_UART2_RTS_B_/_<GPIO3_IO29>_/_IPU2_CSI1_VSYNC_/_IPU1_DI0_PIN14)* J20(EIM_DATA30_/_IPU1_DISP1_DATA21_/_IPU1_DI0_PIN11_/_IPU1_CSI0_DATA03_/_UART3_CTS_B_/_<GPIO3_IO30>_/_USB_H1_OC)* J23(<EIM_CS1>_/_IPU1_DI1_PIN06_/_ECSPI2_MOSI_/_GPIO2_IO24)* J24(<EIM_OE>_/_IPU1_DI1_PIN07_/_ECSPI2_MISO_/_GPIO2_IO25)* K20(<EIM_RW>_/_IPU1_DI1_PIN08_/_ECSPI2_SS0_/_GPIO2_IO26_/_SRC_BOOT_CFG29)* L1(IPU1_CSI0_DATA13_/_EIM_DATA09_/_UART4_RX_DATA_/_<GPIO5_IO31>_/_ARM_TRACE10)* L3(IPU1_CSI0_DATA17_/_EIM_DATA13_/_UART4_CTS_B_/_<GPIO6_IO03>_/_ARM_TRACE14)* L4(IPU1_CSI0_DATA16_/_EIM_DATA12_/_UART4_RTS_B_/_<GPIO6_IO02>_/_ARM_TRACE13)* L6(IPU1_CSI0_DATA19_/_EIM_DATA15_/_UART5_CTS_B_/_<GPIO6_IO05>)* M2(IPU1_CSI0_DATA12_/_EIM_DATA08_/_UART4_TX_DATA_/_<GPIO5_IO30>_/_ARM_TRACE09)* M4(IPU1_CSI0_DATA14_/_EIM_DATA10_/_UART5_TX_DATA_/_<GPIO6_IO00>_/_ARM_TRACE11)* M5(IPU1_CSI0_DATA15_/_EIM_DATA11_/_UART5_RX_DATA_/_<GPIO6_IO01>_/_ARM_TRACE12)* M6(IPU1_CSI0_DATA18_/_EIM_DATA14_/_UART5_RTS_B_/_<GPIO6_IO04>_/_ARM_TRACE15)* N5(IPU1_CSI0_DATA09_/_EIM_DATA07_/_ECSPI2_MOSI_/_KEY_ROW7_/_I2C1_SCL_/_<GPIO5_IO27>_/_ARM_TRACE06)* N6(IPU1_CSI0_DATA08_/_EIM_DATA06_/_ECSPI2_SCLK_/_KEY_COL7_/_I2C1_SDA_/_<GPIO5_IO26>_/_ARM_TRACE05)* N19(IPU1_DI0_DISP_CLK_/_IPU2_DI0_DISP_CLK_/_<GPIO4_IO16>)* N20(IPU1_DI0_PIN03_/_IPU2_DI0_PIN03_/_AUD6_TXFS_/_<GPIO4_IO19>)* N21(IPU1_DI0_PIN15_/_IPU2_DI0_PIN15_/_AUD6_TXC_/_<GPIO4_IO17>)* P4(IPU1_CSI0_HSYNC_/_CCM_CLKO1_/_<GPIO5_IO19>_/_ARM_TRACE_CTL)* P5(KEY_COL5_/_ENET_1588_EVENT0_OUT_/_SPDIF_OUT_/_CCM_CLKO1_/_ECSPI1_RDY_/_<GPIO4_IO05>_/_ENET_TX_ER)* P6(ESAI_TX1_/_ENET_RX_CLK_/_SD3_VSELECT_/_SDMA_EXT_EVENT1_/_ASRC_EXT_CLK_/_<GPIO7_IO13>_/_SNVS_VIO_5_CTL)* R3(ESAI_TX4_RX1_/_ECSPI5_RDY_/_EPIT1_OUT_/_FLEXCAN1_TX_/_UART2_TX_DATA_/_<GPIO1_IO07>_/_SPDIF_LOCK_/_USB_OTG_HOST_MODE)* R5(ESAI_TX5_RX0_/_XTALOSC_REF_CLK_32K_/_EPIT2_OUT_/_FLEXCAN1_RX_/_UART2_RX_DATA_/_<GPIO1_IO08>_/_SPDIF_SR_CLK_/_USB_OTG_PWR_CTL_WAKE)* R20(IPU1_DISP0_DATA13_/_IPU2_DISP0_DATA13_/_AUD5_RXFS_/_<GPIO5_IO07>)* R21(IPU1_DISP0_DATA10_/_IPU2_DISP0_DATA10_/_<GPIO4_IO31>)* R23(IPU1_DISP0_DATA06_/_IPU2_DISP0_DATA06_/_ECSPI3_SS3_/_AUD6_RXC_/_<GPIO4_IO27>)* T20(IPU1_DISP0_DATA21_/_IPU2_DISP0_DATA21_/_ECSPI1_MOSI_/_AUD4_TXD_/_<GPIO5_IO15>)* T23(IPU1_DISP0_DATA11_/_IPU2_DISP0_DATA11_/_<GPIO5_IO05>)* U20(ENET_TX_DATA0_/_ESAI_TX4_RX1_/_<GPIO1_IO30>)* U22(IPU1_DISP0_DATA20_/_IPU2_DISP0_DATA20_/_ECSPI1_SCLK_/_AUD4_TXC_/_<GPIO5_IO14>)* W6(ECSPI1_SS1_/_ENET_RX_DATA2_/_FLEXCAN1_TX_/_KEY_COL2_/_ENET_MDC_/_<GPIO4_IO10>_/_USB_H1_PWR_CTL_WAKE)* W20(MLB_CLK_/_ENET_TX_DATA1_/_ESAI_TX2_RX3_/_ENET_1588_EVENT0_IN_/_<GPIO1_IO29>)* W21(ENET_RX_DATA0_/_ESAI_TX_HF_CLK_/_SPDIF_OUT_/_<GPIO1_IO27>)*

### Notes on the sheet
- CPU - UNUSED PINS
- MISC
- Parallel Camera Interface CSI0
- Serial Display Interface DSI
- FREE for personal and commercial use. See the license.
- Variant:
- Checked by
- Designed by www.fedevel.com

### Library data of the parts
U1 = MCIMX6Q5EYM10AC_v.ORX: as U1 on sheet [12] - CPU - POWER

## Sheet [15] - ETHERNET PHY.SchDoc
size A2; DocumentNumber: 15; SheetNumber: 15; SheetTotal: 31
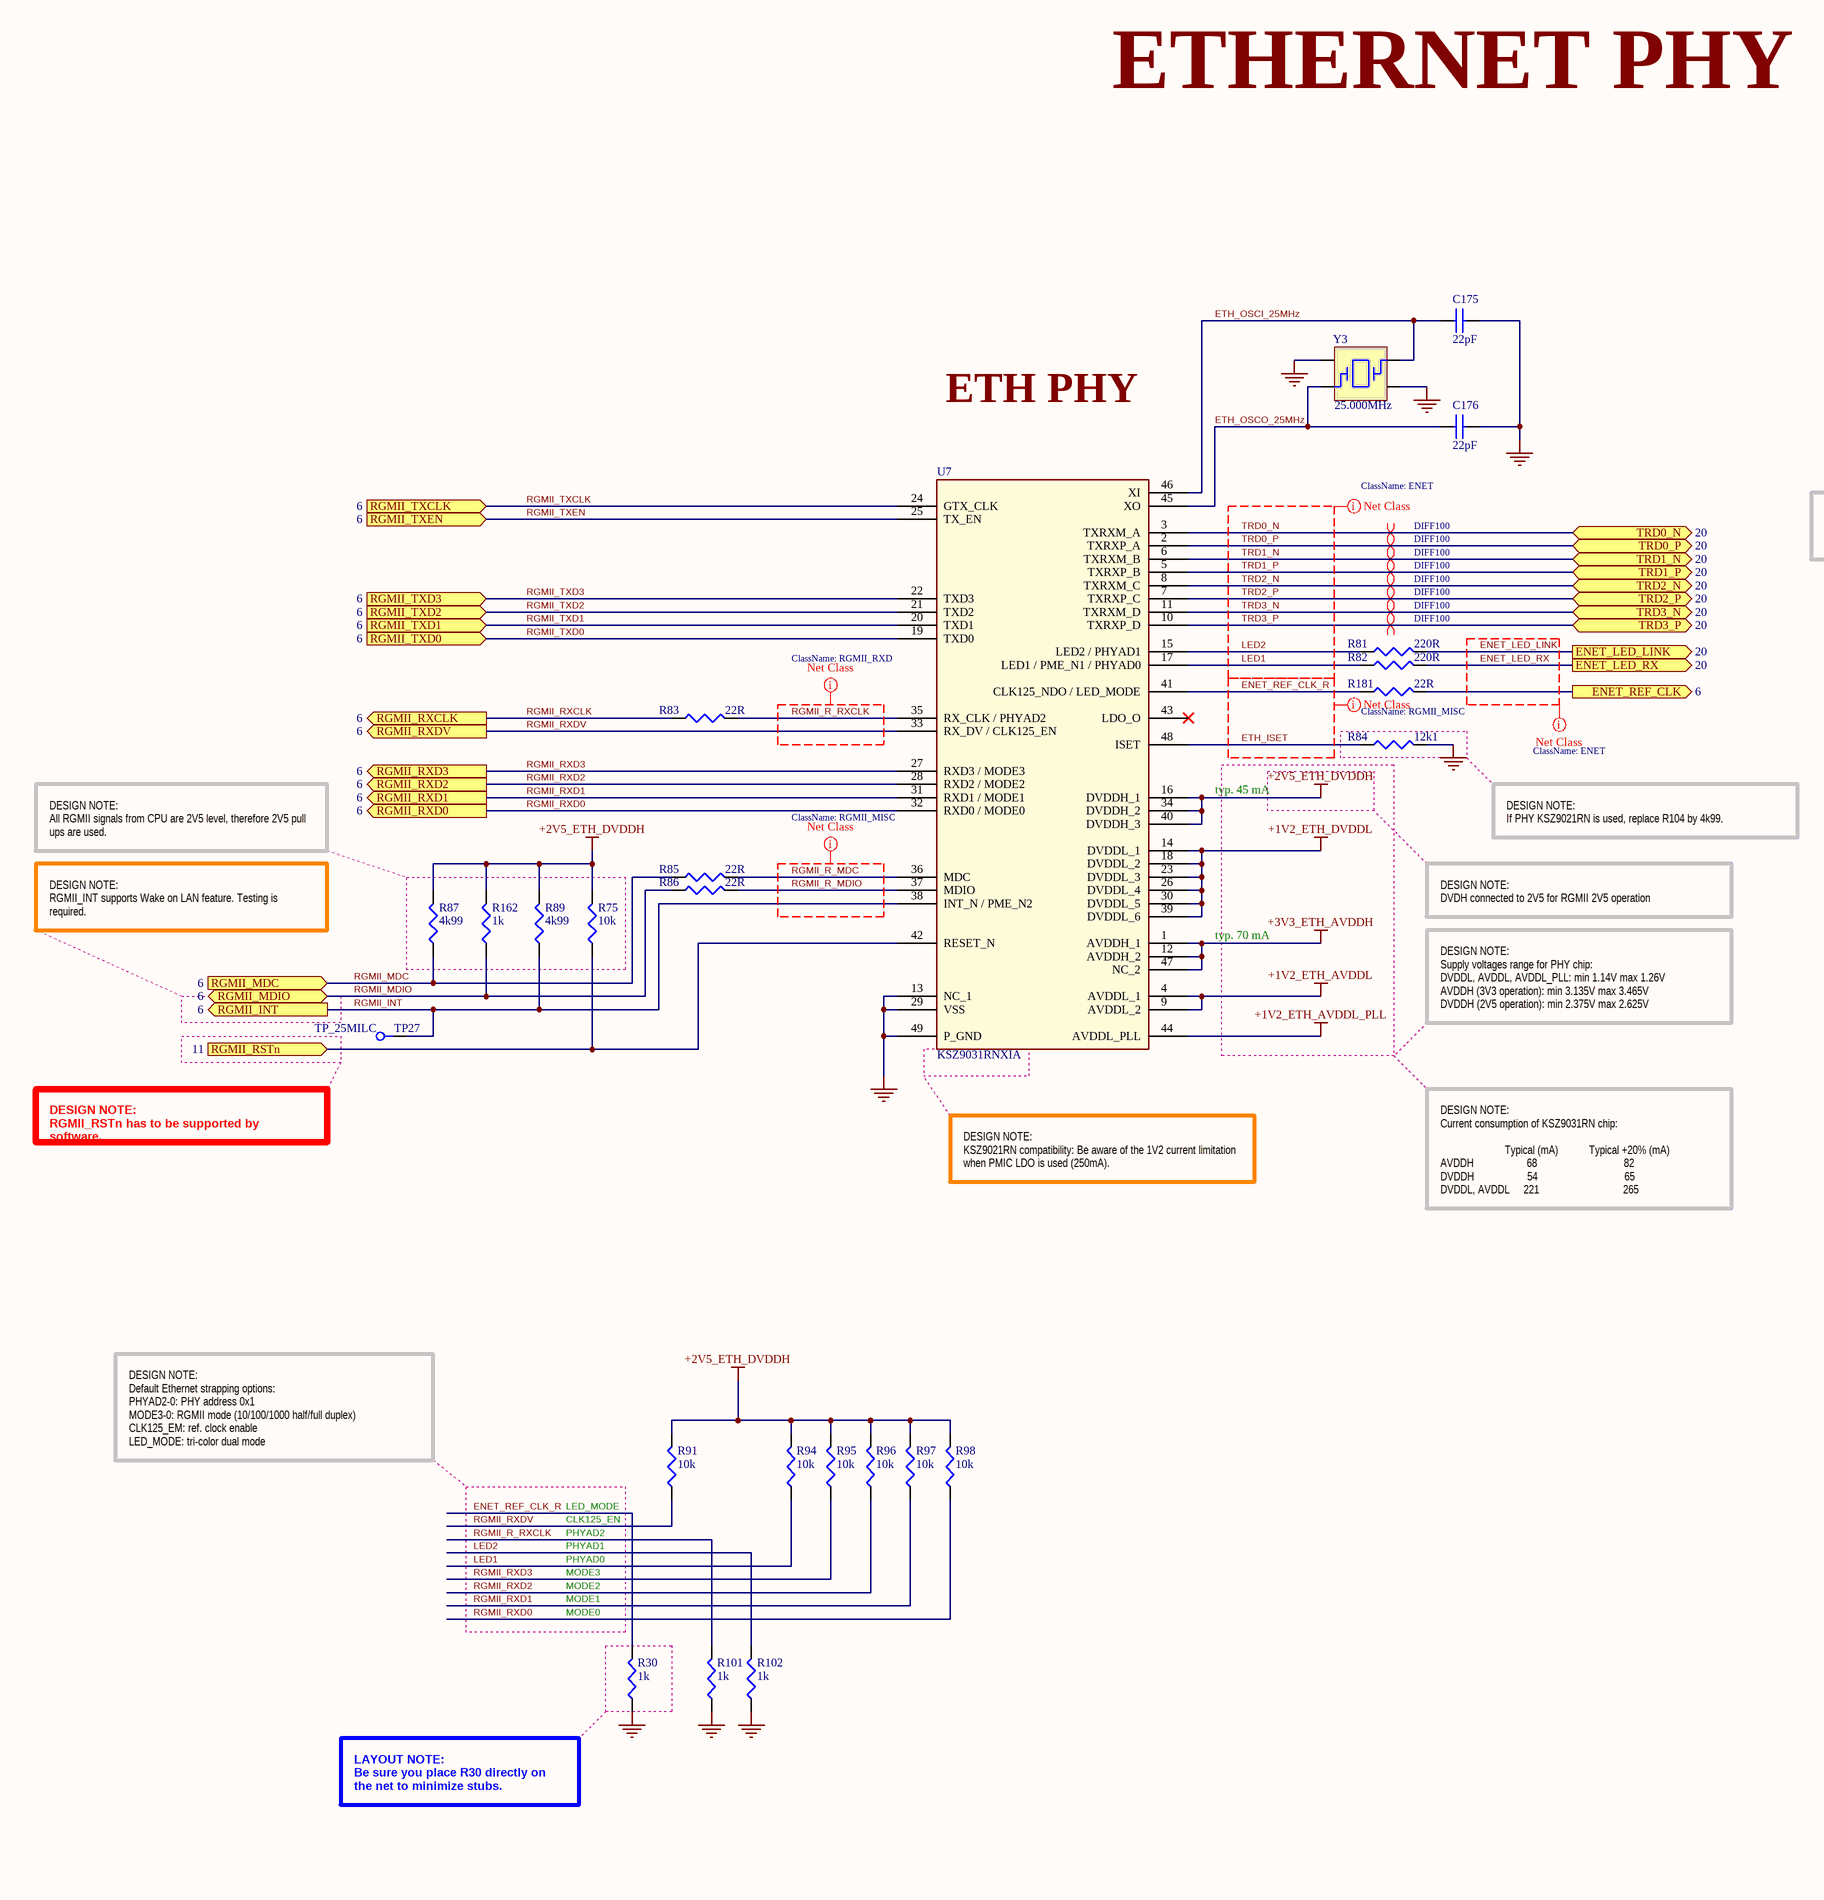
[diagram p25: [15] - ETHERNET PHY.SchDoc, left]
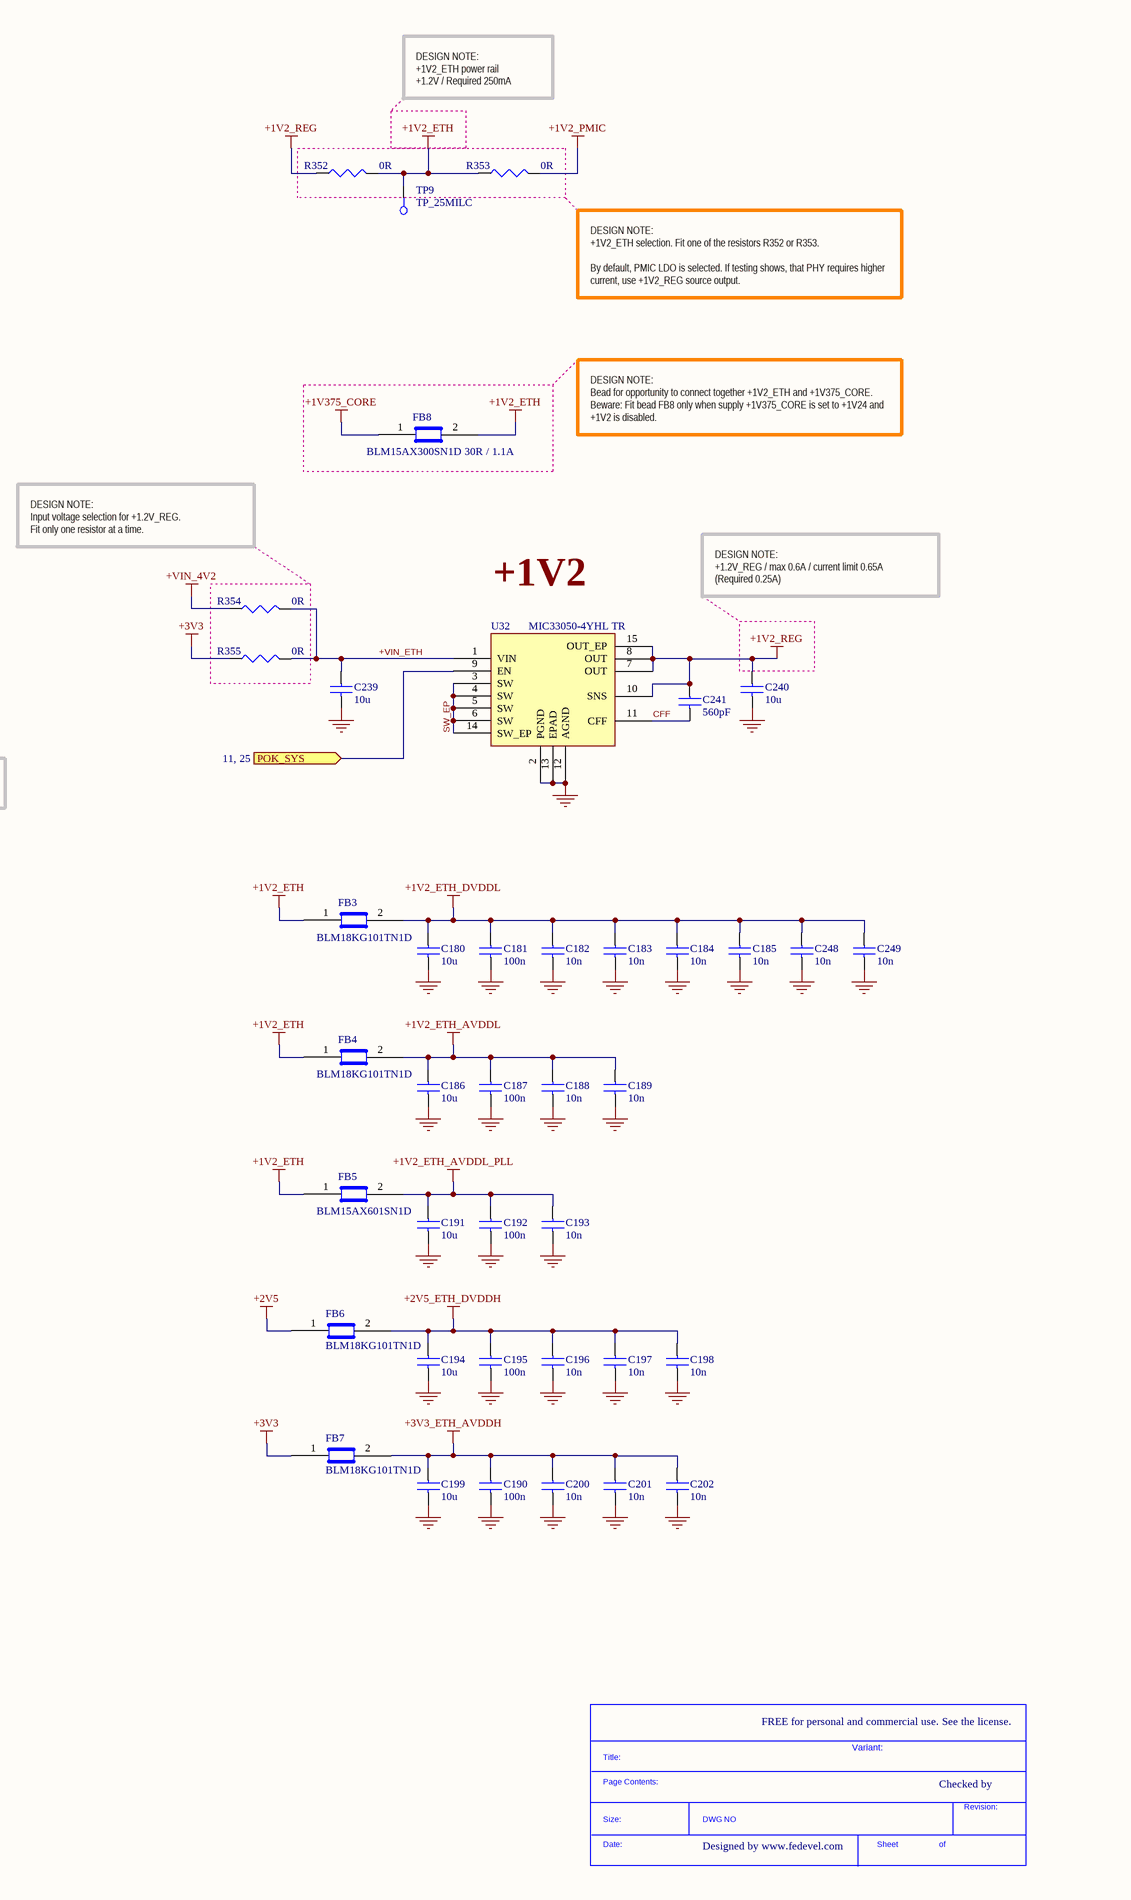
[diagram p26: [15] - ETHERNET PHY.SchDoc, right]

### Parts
(Parts that share a designator on the sheet are numbered #1, #2 ... from top to bottom, then left to right.)
*#16  SDTitleBlock  (value not drawn)  (graphical)
C175  22pF  [C0402]
C176  22pF  [C0402]
C180  10u  [C0603]
C181  100n  [C0402]
C182  10n  [C0402]
C183  10n  [C0402]
C184  10n  [C0402]
C185  10n  [C0402]
C186  10u  [C0603]
C187  100n  [C0402]
C188  10n  [C0402]
C189  10n  [C0402]
C190  100n  [C0402]
C191  10u  [C0603]
C192  100n  [C0402]
C193  10n  [C0402]
C194  10u  [C0603]
C195  100n  [C0402]
C196  10n  [C0402]
C197  10n  [C0402]
C198  10n  [C0402]
C199  10u  [C0603]
C200  10n  [C0402]
C201  10n  [C0402]
C202  10n  [C0402]
C239  10u  [C0603]
C240  10u  [C0603]
C241  560pF  [C0402]
C248  10n  [C0402]
C249  10n  [C0402]
FB3  BLM18KG101TN1D  [C0603]
FB4  BLM18KG101TN1D  [C0603]
FB5  BLM15AX601SN1D  [C0402]
FB6  BLM18KG101TN1D  [C0603]
FB7  BLM18KG101TN1D  [C0603]
FB8  BLM15AX300SN1D 30R / 1.1A  [C0402]
R30  1k  [R0402]
R75  10k  [R0402]
R81  220R  [R0402]
R82  220R  [R0402]
R83  22R  [R0402]
R84  12k1  [R0402]
R85  22R  [R0402]
R86  22R  [R0402]
R87  4k99  [R0402]
R89  4k99  [R0402]
R91  10k  [R0402]
R94  10k  [R0402]
R95  10k  [R0402]
R96  10k  [R0402]
R97  10k  [R0402]
R98  10k  [R0402]
R101  1k  [R0402]
R102  1k  [R0402]
R162  1k  [R0402]
R181  22R  [R0402]
R352  0R  [R0402]
R353  0R  [R0402]
R354  0R  [R0402]
R355  0R  [R0402]
TP9  TP_25MILC  [TP_25C]  (no BOM)
TP27  TP_25MILC  [TP_25C]  (no BOM)
U7  KSZ9031RNXIA  [QFN48_SMALL_EP_7MMX7MM]
U32  MIC33050-4YHL TR  [MLF_3x3_12PINS]
Y3  25.000MHz  [ABM8G]

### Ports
ENET_LED_LINK (out, see 20), ENET_LED_RX (out, see 20), ENET_REF_CLK (out, see 6), POK_SYS (see 11, 25), RGMII_INT (out, see 6), RGMII_MDC (in, see 6), RGMII_MDIO (bidir, see 6), RGMII_RSTn (in, see 11), RGMII_RXCLK (out, see 6), RGMII_RXD0 (out, see 6), RGMII_RXD1 (out, see 6), RGMII_RXD2 (out, see 6), RGMII_RXD3 (out, see 6), RGMII_RXDV (out, see 6), RGMII_TXCLK (in, see 6), RGMII_TXD0 (in, see 6), RGMII_TXD1 (in, see 6), RGMII_TXD2 (in, see 6), RGMII_TXD3 (in, see 6), RGMII_TXEN (in, see 6), TRD0_N (bidir, see 20), TRD0_P (bidir, see 20), TRD1_N (bidir, see 20), TRD1_P (bidir, see 20), TRD2_N (bidir, see 20), TRD2_P (bidir, see 20), TRD3_N (bidir, see 20), TRD3_P (bidir, see 20)

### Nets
+1V2_ETH: FB3.1 FB4.1 FB5.1 FB8.2 R352.2 R353.1 TP9.1
+1V2_ETH_AVDDL: C186.1 C187.1 C188.1 C189.1 FB4.2 U7.4(AVDDL_1) U7.9(AVDDL_2)
+1V2_ETH_AVDDL_PLL: C191.1 C192.1 C193.1 FB5.2 U7.44(AVDDL_PLL)
+1V2_ETH_DVDDL: C180.1 C181.1 C182.1 C183.1 C184.1 C185.1 C248.1 C249.1 FB3.2 U7.14(DVDDL_1) U7.18(DVDDL_2) U7.23(DVDDL_3) U7.26(DVDDL_4) U7.30(DVDDL_5) U7.39(DVDDL_6)
+1V2_PMIC: R353.2
+1V2_REG: C240.1 C241.1 R352.1 U32.7(OUT) U32.8(OUT) U32.10(SNS) U32.15(OUT_EP)
+1V375_CORE: FB8.1
+2V5: FB6.1
+2V5_ETH_DVDDH: C194.1 C195.1 C196.1 C197.1 C198.1 FB6.2 R75.2 R87.2 R89.2 R91.2 R94.2 R95.2 R96.2 R97.2 R98.2 R162.2 U7.16(DVDDH_1) U7.34(DVDDH_2) U7.40(DVDDH_3)
+3V3: FB7.1 R355.1
+3V3_ETH_AVDDH: C190.1 C199.1 C200.1 C201.1 C202.1 FB7.2 U7.1(AVDDH_1) U7.12(AVDDH_2) U7.47(NC_2)
+VIN_4V2: R354.1
GND: C175.2 C176.2 C180.2 C181.2 C182.2 C183.2 C184.2 C185.2 C186.2 C187.2 C188.2 C189.2 C190.2 C191.2 C192.2 C193.2 C194.2 C195.2 C196.2 C197.2 C198.2 C199.2 C200.2 C201.2 C202.2 C239.2 C240.2 C248.2 C249.2 R30.1 R84.2 R101.1 R102.1 U7.13(NC_1) U7.29(VSS) U7.49(P_GND) U32.2(PGND) U32.12(AGND) U32.13(EPAD) Y3.2 Y3.4
+VIN_ETH: C239.1 R354.2 R355.2 U32.1(VIN)
CFF: C241.2 U32.11(CFF)
ENET_LED_LINK: R81.2 ; port ENET_LED_LINK
ENET_LED_RX: R82.2 ; port ENET_LED_RX
ENET_REF_CLK: R181.2 ; port ENET_REF_CLK
ENET_REF_CLK_R: R30.2 R181.1 U7.41(CLK125_NDO_/_LED_MODE)
ETH_ISET: R84.1 U7.48(ISET)
ETH_OSCI_25MHz: C175.1 U7.46(XI) Y3.3
ETH_OSCO_25MHz: C176.1 U7.45(XO) Y3.1
LED1: R82.1 R94.1 U7.17(LED1_/_PME_N1_/_PHYAD0)
LED2: R81.1 R102.2 U7.15(LED2_/_PHYAD1)
POK_SYS: U32.9(EN) ; port POK_SYS
RGMII_INT: R89.1 TP27.1 U7.38(INT_N_/_PME_N2) ; port RGMII_INT
RGMII_MDC: R85.1 R87.1 ; port RGMII_MDC
RGMII_MDIO: R86.1 R162.1 ; port RGMII_MDIO
RGMII_R_MDC: R85.2 U7.36(MDC)
RGMII_R_MDIO: R86.2 U7.37(MDIO)
RGMII_R_RXCLK: R83.2 R101.2 U7.35(RX_CLK_/_PHYAD2)
RGMII_RSTn: R75.1 U7.42(RESET_N) ; port RGMII_RSTn
RGMII_RXCLK: R83.1 ; port RGMII_RXCLK
RGMII_RXD0: R98.1 U7.32(RXD0_/_MODE0) ; port RGMII_RXD0
RGMII_RXD1: R97.1 U7.31(RXD1_/_MODE1) ; port RGMII_RXD1
RGMII_RXD2: R96.1 U7.28(RXD2_/_MODE2) ; port RGMII_RXD2
RGMII_RXD3: R95.1 U7.27(RXD3_/_MODE3) ; port RGMII_RXD3
RGMII_RXDV: R91.1 U7.33(RX_DV_/_CLK125_EN) ; port RGMII_RXDV
RGMII_TXCLK: U7.24(GTX_CLK) ; port RGMII_TXCLK
RGMII_TXD0: U7.19(TXD0) ; port RGMII_TXD0
RGMII_TXD1: U7.20(TXD1) ; port RGMII_TXD1
RGMII_TXD2: U7.21(TXD2) ; port RGMII_TXD2
RGMII_TXD3: U7.22(TXD3) ; port RGMII_TXD3
RGMII_TXEN: U7.25(TX_EN) ; port RGMII_TXEN
SW_EP: U32.3(SW) U32.4(SW) U32.5(SW) U32.6(SW) U32.14(SW_EP)
TRD0_N: U7.3(TXRXM_A) ; port TRD0_N
TRD0_P: U7.2(TXRXP_A) ; port TRD0_P
TRD1_N: U7.6(TXRXM_B) ; port TRD1_N
TRD1_P: U7.5(TXRXP_B) ; port TRD1_P
TRD2_N: U7.8(TXRXM_C) ; port TRD2_N
TRD2_P: U7.7(TXRXP_C) ; port TRD2_P
TRD3_N: U7.11(TXRXM_D) ; port TRD3_N
TRD3_P: U7.10(TXRXP_D) ; port TRD3_P

Not connected (* = marked no-connect by the designer): U7 43(LDO_O)*

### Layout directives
differential pair; net class DIFF100: TRD0_N, TRD0_P, TRD1_N, TRD1_P, TRD2_N, TRD2_P, TRD3_N, TRD3_P
net class ENET: ENET_LED_LINK, ENET_LED_RX, LED1, LED2, TRD0_N, TRD0_P, TRD1_N, TRD1_P, TRD2_N, TRD2_P, TRD3_N, TRD3_P
net class RGMII_MISC: ENET_REF_CLK_R, ETH_ISET, RGMII_R_MDC, RGMII_R_MDIO
net class RGMII_RXD: RGMII_R_RXCLK

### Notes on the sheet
- ETHERNET PHY
- DESIGN NOTE:
  +1V2_ETH power rail
  +1.2V / Required 250mA
- DESIGN NOTE:
  +1V2_ETH selection. Fit one of the resistors R352 or R353.
  By default, PMIC LDO is selected. If testing shows, that PHY requires higher current, use +1V2_REG source output.
- ETH PHY
- DESIGN NOTE:
  Bead for opportunity to connect together +1V2_ETH and +1V375_CORE. Beware: Fit bead FB8 only when supply +1V375_CORE is set to +1V24 and +1V2 is disabled.
- DESIGN NOTE:
  Input voltage selection for +1.2V_REG.
  Fit only one resistor at a time.
- +1V2
- DESIGN NOTE:
  +1.2V_REG / max 0.6A / current limit 0.65A
  (Required 0.25A)
- typ. 45 mA
- DESIGN NOTE:
  If PHY KSZ9021RN is used, replace R104 by 4k99.
- DESIGN NOTE:
  All RGMII signals from CPU are 2V5 level, therefore 2V5 pull ups are used.
- DESIGN NOTE:
  RGMII_INT supports Wake on LAN feature. Testing is required.
- typ. 70 mA
- DESIGN NOTE:
  DVDH connected to 2V5 for RGMII 2V5 operation
- DESIGN NOTE:
  Supply voltages range for PHY chip:
  DVDDL, AVDDL, AVDDL_PLL: min 1.14V max 1.26V
  AVDDH (3V3 operation): min 3.135V max 3.465V
  DVDDH (2V5 operation): min 2.375V max 2.625V
- DESIGN NOTE:
  RGMII_RSTn has to be supported by software.
- DESIGN NOTE:
  KSZ9021RN compatibility: Be aware of the 1V2 current limitation when PMIC LDO is used (250mA).
- DESIGN NOTE:
  Current consumption of KSZ9031RN chip:
  Typical (mA)           Typical +20% (mA)
  AVDDH                   68                               82
  DVDDH                   54                               65
  DVDDL, AVDDL     221                              265
- DESIGN NOTE:
  Default Ethernet strapping options:
  PHYAD2-0: PHY address 0x1
  MODE3-0: RGMII mode (10/100/1000 half/full duplex)
  CLK125_EM: ref. clock enable
  LED_MODE: tri-color dual mode
- LED_MODE
- CLK125_EN
- PHYAD2
- PHYAD1
- PHYAD0
- MODE0
- MODE1
- MODE2
- MODE3
- LAYOUT NOTE:
  Be sure you place R30 directly on the net to minimize stubs.
- FREE for personal and commercial use. See the license.
- Variant:
- Checked by
- Designed by www.fedevel.com

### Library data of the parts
C175 C176 = C1005C0G1H220J: CAP CER 22PF 50V C0G 5% 0402; Manufacturer: TDK Corporation; .Checked PCB: used; Temperature Coefficient: C0G, NP0
C180 C186 C191 C194 C199 C239 C240 = C1608X5R0J106M: as C227 on sheet [18] - PCIE MINI
C181 C187 C190 C192 C195 = C1005X5R1H104K: as C218 on sheet [18] - PCIE MINI
C182-C185 C188 C189 C193 C196-C198 C200-C202 C248 C249 = C1005X7R1H103K: CAP CER 10000PF 50V 10% X7R 0402; Manufacturer: TDK Corporation; Value: 10nF; .Checked PCB: used
C241 = GRM1555C1H561JA01D: CAP CER 560PF 50V C0G 0402; Manufacturer: Murata Electronics North America; .Checked PCB: used; Tolerance: ±5%; Temperature Coefficient: C0G, NP0
FB3 FB4 FB6 FB7 = BLM18KG101TN1D: FERRITE CHIP 100 OHM BEAD 0603 3A; Manufacturer: Murata Electronics North America; .Checked PCB: used; Impedance @ Frequency: 100 Ohm @ 100MHz; DC Resistance (DCR): 30 mOhm Max; Filter Type: Differential Mode - Single; Number of Lines: 1
FB5 = BLM15AX601SN1D: FERRITE CHIP 600 OHM 0402 420mA; Manufacturer: Murata Electronics North America; .Checked PCB: used; Impedance @ Frequency: 600 Ohm @ 100MHz; DC Resistance (DCR): 340 mOhm Max; Filter Type: Differential Mode - Single; Number of Lines: 1
FB8 = BLM15AX300SN1D: FERRITE CHIP 30 OHM 1100MA 0402; Manufacturer: Murata Electronics North America; Impedance @ Frequency: 30 Ohm @ 100MHz; DC Resistance (DCR): 60 mOhm Max; Filter Type: Differential Mode - Single; Number of Lines: 1; .Checked PCB: MM
R30 R101 R102 R162 = RC0402FR-071KL: RES 1.00K OHM 1/16W 1% 0402 SMD; Manufacturer: Yageo; Power (Watts): 0.063W, 1/16W; .Checked PCB: used; Temperature Coefficient: ±100ppm/°C
R75 R91 R94-R98 = RC0402FR-0710KL: as R197 on sheet [18] - PCIE MINI
R81 R82 = RC0402FR-07220RL: RES 220 OHM 1/16W 1% 0402 SMD; Manufacturer: Yageo; Resistance (Ohms): 220; Power (Watts): 0.063W, 1/16W; .Checked PCB: used; Temperature Coefficient: ±100ppm/°C
R83 R85 R86 R181 = RC0402FR-0722RL: RES 22.0 OHM 1/16W 1% 0402 SMD; Manufacturer: Yageo; Resistance (Ohms): 22; Power (Watts): 0.063W, 1/16W; .Checked PCB: used; Temperature Coefficient: ±100ppm/°C
R84 = RC0402FR-0712K1L: RES SMD 12.1K OHM 1% 1/16W 0402; Manufacturer: Yageo; Power (Watts): 0.063W, 1/16W; Temperature Coefficient: ±100ppm/°C; .Creator: MM
R87 R89 = RMCF0402FT4K99: RES TF 4.99K OHM 1% 1/16W 0402; Manufacturer: Stackpole Electronics Inc; Power (Watts): 0.063W, 1/16W; .Checked PCB: used; Temperature Coefficient: ±100ppm/°C
R352-R355 = RC0402JR-070RL: as R74 on sheet [12] - CPU - POWER
TP9 TP27 = TP_25MILC: Test Point 25mil
U7 = KSZ9031RNXIA: IC TXRX ETHERNET 48-QFN; Manufacturer: Micrel Inc; Number of Drivers/Receivers: 4/4; Duplex: Full; Voltage - Supply: 1.8V, 2.5V, 3.3V; .Creator: MM
U32 = MIC33050-4YHL TR: IC PWM REG 600mA 1.2V 12-MLF; Manufacturer: Micrel Inc; .Checked PCB: used; Voltage - Input: 2.7 V ~ 5.5 V; Output Type: Fixed; Number of Outputs: 1; PWM Type: Current Mode; Frequency - Switching: 4MHz; Synchronous Rectifier: Yes
Y3 = ABM8G-25.000MHZ-18-D2Y-T: CRYSTAL 25MHZ 18PF SMD; Manufacturer: Abracon Corporation; Frequency Stability: ±30ppm; Frequency Tolerance: ±20ppm; ESR (Equivalent Series Resistance): 60 Ohm; Operating Mode: Fundamental; .Checked PCB: MM

## Sheet [19] - USB.SchDoc
size A2; DocumentNumber: 19; SheetNumber: 19; SheetTotal: 31
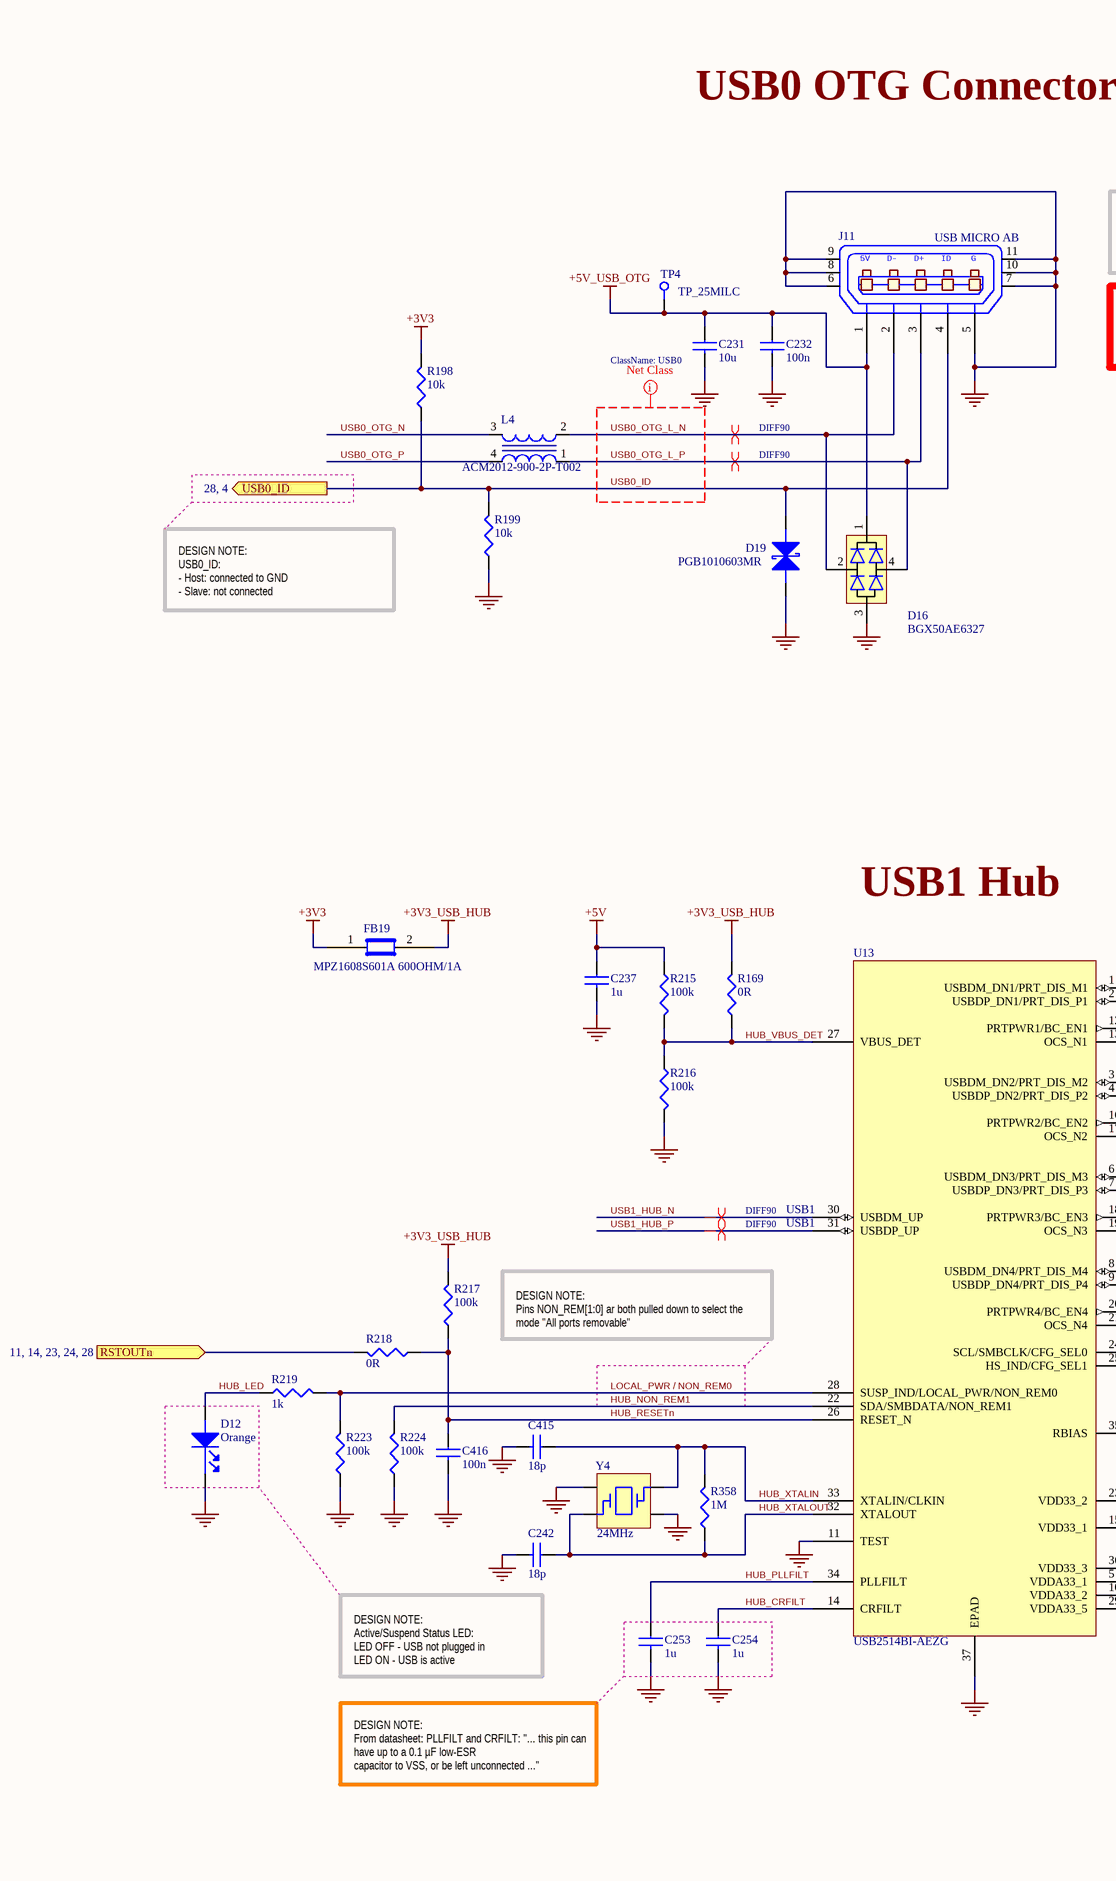
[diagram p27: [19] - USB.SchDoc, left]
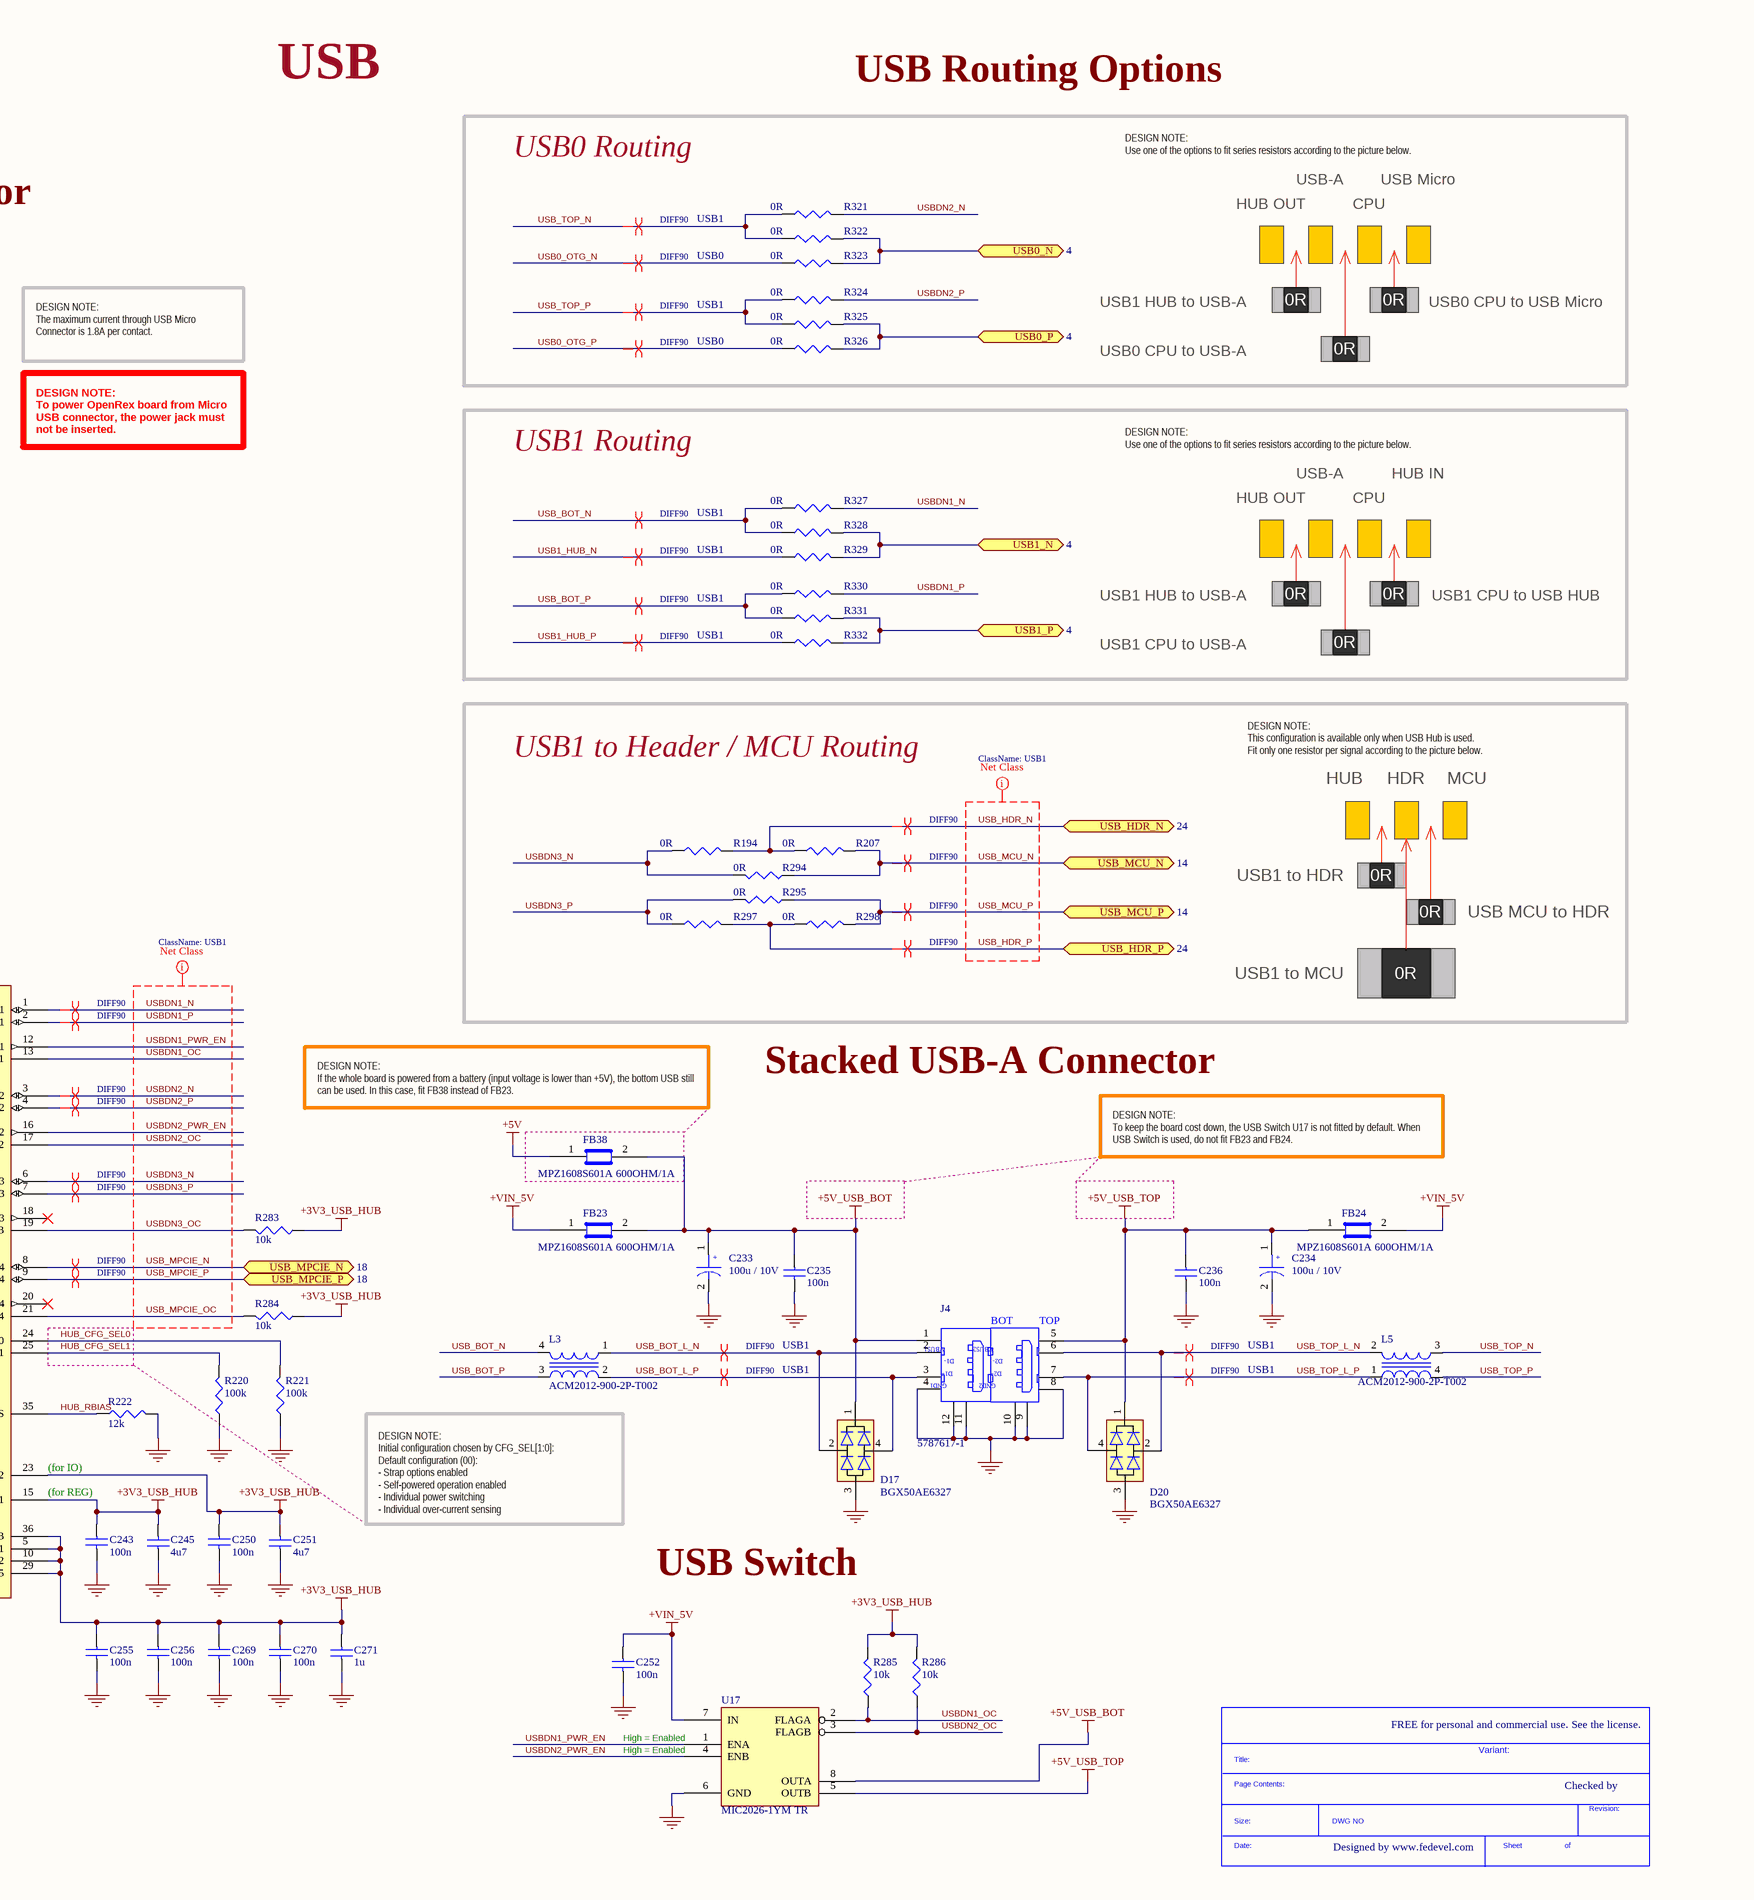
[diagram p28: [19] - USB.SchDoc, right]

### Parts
(Parts that share a designator on the sheet are numbered #1, #2 ... from top to bottom, then left to right.)
*#17  SDTitleBlock  (value not drawn)  (graphical)
C231  10u  [C0603]
C232  100n  [C0402]
C233  100u / 10V  [C2312]
C234  100u / 10V  [C2312]
C235  100n  [C0402]
C236  100n  [C0402]
C237  1u  [C0402]
C242  18p  [C0402]
C243  100n  [C0402]
C245  4u7  [C0402]
C250  100n  [C0402]
C251  4u7  [C0402]
C252  100n  [C0402]
C253  1u  [C0402]
C254  1u  [C0402]
C255  100n  [C0402]
C256  100n  [C0402]
C269  100n  [C0402]
C270  100n  [C0402]
C271  1u  [C0402]
C415  18p  [C0402]
C416  100n  [C0402]
D12  Orange  [LED_0603]
D16  BGX50AE6327  [SOT143]
D17  BGX50AE6327  [SOT143]
D19  PGB1010603MR  [C0603]
D20  BGX50AE6327  [SOT143]
FB19  MPZ1608S601A 600OHM/1A  [C0603]
FB23  MPZ1608S601A 600OHM/1A  [C0603]
FB24  MPZ1608S601A 600OHM/1A  [C0603]
FB38  MPZ1608S601A 600OHM/1A  [C0603]
J4  5787617-1  [USB-2A]
J11  USB MICRO AB  [USB_Micro_AB]
L3  ACM2012-900-2P-T002  [ACM2012]
L4  ACM2012-900-2P-T002  [ACM2012]
L5  ACM2012-900-2P-T002  [ACM2012]
R169  0R  [R0402]
R194  0R  [R0402]
R198  10k  [R0402]
R199  10k  [R0402]
R207  0R  [R0402]
R215  100k  [R0402]
R216  100k  [R0402]
R217  100k  [R0402]
R218  0R  [R0402]
R219  1k  [R0402]
R220  100k  [R0402]
R221  100k  [R0402]
R222  12k  [R0402]
R223  100k  [R0402]
R224  100k  [R0402]
R283  10k  [R0402]
R284  10k  [R0402]
R285  10k  [R0402]
R286  10k  [R0402]
R294  0R  [R0805_small]
R295  0R  [R0805_small]
R297  0R  [R0402]
R298  0R  [R0402]
R321  0R  [R0402]
R322  0R  [R0402]
R323  0R  [R0402]
R324  0R  [R0402]
R325  0R  [R0402]
R326  0R  [R0402]
R327  0R  [R0402]
R328  0R  [R0402]
R329  0R  [R0402]
R330  0R  [R0402]
R331  0R  [R0402]
R332  0R  [R0402]
R358  1M  [R0402]
TP4  TP_25MILC  [TP_25C]  (no BOM)
U13  USB2514BI-AEZG  [QFN36_6mmx6mm]
U17  MIC2026-1YM TR  [8_SOIC_3.9MM]
Y4  24MHz  [ABM8]

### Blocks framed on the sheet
USB0 Routing: R321-R326
USB1 Routing: R327-R332
USB1 to Header / MCU Routing: R194 R207 R294 R295 R297 R298

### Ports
RSTOUTn (see 11, 14, 23, 24, 28), USB0_ID (see 28, 4), USB0_N (bidir, see 4), USB0_P (bidir, see 4), USB1_N (bidir, see 4), USB1_P (bidir, see 4), USB_HDR_N (bidir, see 24), USB_HDR_P (bidir, see 24), USB_MCU_N (bidir, see 14), USB_MCU_P (bidir, see 14), USB_MPCIE_N (bidir, see 18), USB_MPCIE_P (bidir, see 18)

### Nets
+3V3: FB19.1 R198.2
+3V3_USB_HUB: C243.1 C245.2 C250.1 C251.2 C255.1 C256.1 C269.1 C270.1 C271.2 FB19.2 R169.2 R217.2 R283.1 R284.1 R285.2 R286.2 U13.5(VDDA33_1) U13.10(VDDA33_2) U13.15(VDD33_1) U13.23(VDD33_2) U13.29(VDDA33_5) U13.36(VDD33_3)
+5V: C237.1 FB38.1 R215.1
+5V_USB_BOT: C233.1 C235.1 D17.1 FB23.2 FB38.2 J4.1(VBUS) U17.8(OUTA)
+5V_USB_OTG: C231.1 C232.1 D16.1 J11.1(P1) TP4.1
+5V_USB_TOP: C234.1 C236.1 D20.1 FB24.1 J4.5(VBUS2) U17.5(OUTB)
+VIN_5V: C252.1 FB23.1 FB24.2 U17.7(IN)
GND: C231.2 C232.2 C233.2 C234.2 C235.2 C236.2 C237.2 C242.2 C243.2 C245.1 C250.2 C251.1 C252.2 C253.2 C254.2 C255.2 C256.2 C269.2 C270.2 C271.1 C415.2 C416.2 D12.1(cathode) D16.3 D17.3 D19.2 D20.3 J4.4(GND) J4.8(GND) J4.9(SHIELD) J4.10(SHIELD) J4.11(SHIELD) J4.12(SHIELD) J11.5(P5) J11.6 J11.7 J11.8 J11.9 J11.10 J11.11 R199.1 R216.2 R220.1 R221.1 R222.2 R223.1 R224.1 U13.11(TEST) U13.37(EPAD) U17.6(GND) Y4.2 Y4.4
HUB_CFG_SEL0: R221.2 U13.24(SCL/SMBCLK/CFG_SEL0)
HUB_CFG_SEL1: R220.2 U13.25(HS_IND/CFG_SEL1)
HUB_CRFILT: C254.1 U13.14(CRFILT)
HUB_LED: D12.2(ANODE) R219.1
HUB_NON_REM1: R224.2 U13.22(SDA/SMBDATA/NON_REM1)
HUB_PLLFILT: C253.1 U13.34(PLLFILT)
HUB_RBIAS: R222.1 U13.35(RBIAS)
HUB_RESETn: C416.1 R217.1 R218.1 U13.26(RESET_N)
HUB_VBUS_DET: R169.1 R215.2 R216.1 U13.27(VBUS_DET)
HUB_XTALIN: C415.1 R358.2 U13.33(XTALIN/CLKIN) Y4.3
HUB_XTALOUT: C242.1 R358.1 U13.32(XTALOUT) Y4.1
LOCAL_PWR / NON_REM0: R219.2 R223.2 U13.28(SUSP_IND/LOCAL_PWR/NON_REM0)
RSTOUTn: R218.2 ; port RSTOUTn
USB0_ID: D19.1 J11.4(P4) R198.1 R199.2 ; port USB0_ID
USB0_N: R322.2 R323.2 ; port USB0_N
USB0_OTG_L_N: D16.2 J11.2(P2) L4.2
USB0_OTG_L_P: D16.4 J11.3(P3) L4.1
USB0_OTG_N: L4.3 R323.1
USB0_OTG_P: L4.4 R326.1
USB0_P: R325.2 R326.2 ; port USB0_P
USB1_HUB_N: R329.1 U13.30(USBDM_UP)
USB1_HUB_P: R332.1 U13.31(USBDP_UP)
USB1_N: R328.2 R329.2 ; port USB1_N
USB1_P: R331.2 R332.2 ; port USB1_P
USB_BOT_L_N: D17.2 J4.2(D-) L3.1
USB_BOT_L_P: D17.4 J4.3(D+) L3.2
USB_BOT_N: L3.4 R327.1 R328.1
USB_BOT_P: L3.3 R330.1 R331.1
USB_HDR_N: R194.2 R207.1 ; port USB_HDR_N
USB_HDR_P: R297.2 R298.1 ; port USB_HDR_P
USB_MCU_N: R207.2 R294.2 ; port USB_MCU_N
USB_MCU_P: R295.1 R298.2 ; port USB_MCU_P
USB_MPCIE_N: U13.8(USBDM_DN4/PRT_DIS_M4) ; port USB_MPCIE_N
USB_MPCIE_OC: R284.2 U13.21(OCS_N4)
USB_MPCIE_P: U13.9(USBDP_DN4/PRT_DIS_P4) ; port USB_MPCIE_P
USB_TOP_L_N: D20.2 J4.6(D2-) L5.2
USB_TOP_L_P: D20.4 J4.7(D2+) L5.1
USB_TOP_N: L5.3 R321.1 R322.1
USB_TOP_P: L5.4 R324.1 R325.1
USBDN1_N: R327.2 U13.1(USBDM_DN1/PRT_DIS_M1)
USBDN1_OC: R285.1 U13.13(OCS_N1) U17.2(FLAGA)
USBDN1_P: R330.2 U13.2(USBDP_DN1/PRT_DIS_P1)
USBDN1_PWR_EN: U13.12(PRTPWR1/BC_EN1) U17.1(ENA)
USBDN2_N: R321.2 U13.3(USBDM_DN2/PRT_DIS_M2)
USBDN2_OC: R286.1 U13.17(OCS_N2) U17.3(FLAGB)
USBDN2_P: R324.2 U13.4(USBDP_DN2/PRT_DIS_P2)
USBDN2_PWR_EN: U13.16(PRTPWR2/BC_EN2) U17.4(ENB)
USBDN3_N: R194.1 R294.1 U13.6(USBDM_DN3/PRT_DIS_M3)
USBDN3_OC: R283.2 U13.19(OCS_N3)
USBDN3_P: R295.2 R297.1 U13.7(USBDP_DN3/PRT_DIS_P3)

Not connected (* = marked no-connect by the designer): U13 18(PRTPWR3/BC_EN3)* 20(PRTPWR4/BC_EN4)*

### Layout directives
differential pair; net class DIFF90: USB0_OTG_L_N, USB0_OTG_L_P, USB_HDR_N, USB_HDR_P, USB_MCU_N, USB_MCU_P, USB_MPCIE_N, USB_MPCIE_P, USBDN1_N, USBDN1_P, USBDN2_N, USBDN2_P, USBDN3_N, USBDN3_P
net class USB1: USB_HDR_N, USB_HDR_P, USB_MCU_N, USB_MCU_P, USB_MPCIE_N, USB_MPCIE_OC, USB_MPCIE_P, USBDN1_N, USBDN1_OC, USBDN1_P, USBDN1_PWR_EN, USBDN2_N, USBDN2_OC, USBDN2_P, USBDN2_PWR_EN, USBDN3_N, USBDN3_OC, USBDN3_P
net class USB0: USB0_ID, USB0_OTG_L_N, USB0_OTG_L_P
differential pair; net class DIFF90; net class USB1: USB1_HUB_N, USB1_HUB_P, USB_BOT_L_N, USB_BOT_L_P, USB_BOT_N, USB_BOT_P, USB_TOP_L_N, USB_TOP_L_P, USB_TOP_N, USB_TOP_P
differential pair; net class DIFF90; net class USB0: USB0_OTG_N, USB0_OTG_P

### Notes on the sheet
- USB
- USB Routing Options
- USB0 OTG Connector
- DESIGN NOTE:
  Use one of the options to fit series resistors according to the picture below.
- HUB OUT
- USB-A
- CPU
- USB Micro
- USB1 HUB to USB-A
- 0R
- USB0 CPU to USB Micro
- DESIGN NOTE:
  The maximum current through USB Micro Connector is 1.8A per contact.
- USB0 CPU to USB-A
- DESIGN NOTE:
  To power OpenRex board from Micro USB connector, the power jack must not be inserted.
- HUB IN
- USB1 CPU to USB HUB
- DESIGN NOTE:
  USB0_ID:
  - Host: connected to GND
  - Slave: not connected
- USB1 CPU to USB-A
- DESIGN NOTE:
  This configuration is available only when USB Hub is used.
  Fit only one resistor per signal according to the picture below.
- HUB
- HDR
- MCU
- USB1 to HDR
- USB1 Hub
- USB MCU to HDR
- USB1 to MCU
- DESIGN NOTE:
  If the whole board is powered from a battery (input voltage is lower than +5V), the bottom USB still can be used. In this case, fit FB38 instead of FB23.
- Stacked USB-A Connector
- DESIGN NOTE:
  To keep the board cost down, the USB Switch U17 is not fitted by default. When USB Switch is used, do not fit FB23 and FB24.
- DESIGN NOTE:
  Pins NON_REM[1:0] ar both pulled down to select the mode "All ports removable"
- (for IO)
- (for REG)
- DESIGN NOTE:
  Initial configuration chosen by CFG_SEL[1:0]:
  Default configuration (00):
  - Strap options enabled
  - Self-powered operation enabled
  - Individual power switching
  - Individual over-current sensing
- USB Switch
- DESIGN NOTE:
  Active/Suspend Status LED:
  LED OFF - USB not plugged in
  LED ON - USB is active
- DESIGN NOTE:
  From datasheet: PLLFILT and CRFILT: "... this pin can have up to a 0.1 µF low-ESR
  capacitor to VSS, or be left unconnected ..."
- (near U17) High = Enabled
- FREE for personal and commercial use. See the license.
- Variant:
- Checked by
- Designed by www.fedevel.com

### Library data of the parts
C231 = C1608X5R0J106M: as C227 on sheet [18] - PCIE MINI
C232 C235 C236 C243 C250 C252 C255 C256 C269 C270 C416 = C1005X5R1H104K: as C218 on sheet [18] - PCIE MINI
C233 C234 = TPSC107K010R0150: CAP TANT 100UF 10V 10% 2312; Manufacturer: AVX Corporation; Manufacturer Size Code: C; Capacitance: 100µF; ESR (Equivalent Series Resistance): 150 mOhm; Type: Molded; .Creator: MM
C237 C253 C254 C271 = C1005X5R1C105K: CAP CER 1.0UF 16V X5R 0402; Manufacturer: TDK Corporation; Capacitance: 1.0µF; Value: 1uF; .Checked PCB: used; Tolerance: ±10%
C242 C415 = C1005C0G1H180J: CAP CER 18PF 50V C0G 5% 0402; Manufacturer: TDK Corporation; .Checked PCB: used; Temperature Coefficient: C0G, NP0
C245 C251 = C1005X5R1A475M: as C262-C264 on sheet [18] - PCIE MINI
D12 = LO L29K-H2K1-24-Z: LED SMARTLED ORANGE 606NM 0603; Manufacturer: OSRAM Opto Semiconductors Inc; Millicandela Rating: 6.3mcd; Voltage - Forward (Vf) Typ: 1.8V; Current - Test: 2mA; Wavelength - Peak: 610nm; Viewing Angle: 160°; Lens Type: Diffused; Lens Style/Size: Rectangle with Flat Top, 1.3mm x 0.8mm; Luminous Flux @ Current - Test: 25 mlm; .Checked PCB: used
D16 D17 D20 = BGX50AE6327: DIODE SWITCHING 50V SOT-143; Manufacturer: Infineon Technologies; .Checked PCB: used; Current - DC Forward (If): 140mA; Diode Type: Single Phase; Speed: Small Signal =< 200mA (Io), Any Speed; Reverse Recovery Time (trr): 6ns
D19 = PGB1010603MR: SUPPRESSOR ESD 24VDC 0603 SMD; Manufacturer: Littelfuse Inc; Voltage - Reverse Standoff (Typ): 24V; Polarization: Bidirectional; .Creator: MM; .Checked PCB: used
FB19 FB23 FB24 FB38 = MPZ1608S601A: FERRITE CHIP BEAD 600 OHM SMD 1A; Manufacturer: TDK Corporation; Impedance @ Frequency: 600 Ohm @ 100MHz; DC Resistance (DCR): 150 mOhm Max; Filter Type: Differential Mode - Single; Number of Lines: 1; .Checked PCB: used
J4 = 5787617-1_v1.1: CONN RCPT R/A 4OVER4POS GOLD PCB; Manufacturer: TE Connectivity; .Checked PCB: used; .Checked SCH: MM; Connector Type: USB - A, Stacked; Number of Contacts: 8; Gender: Receptacle; Specifications: USB 2.0
J11 = 0475890001: CONN RCPT MICRO USB AB R/A SMD; Manufacturer: Molex Inc; Connector Type: USB - micro AB; Number of Contacts: 5; Gender: Receptacle; .Creator: MM; .Checked PCB: used
L3-L5 = ACM2012-900-2P-T002: as L6 on sheet [18] - PCIE MINI
R169 R194 R207 R218 R297 R298 R321-R332 = RC0402JR-070RL: as R74 on sheet [12] - CPU - POWER
R198 R199 R283-R286 = RC0402FR-0710KL: as R197 on sheet [18] - PCIE MINI
R215-R217 R220 R221 R223 R224 = RMCF0402FT100K: RES 100K OHM 1/16W 1% 0402 SMD; Manufacturer: Stackpole Electronics Inc; Power (Watts): 0.063W, 1/16W; .Checked PCB: used; Temperature Coefficient: ±100ppm/°C
R219 = RC0402FR-071KL: as R30 on sheet [15] - ETHERNET PHY
R222 = RC0402FR-0712KL: RES 12.0K OHM 1/16W 1% 0402 SMD; Manufacturer: Yageo; Power (Watts): 0.063W, 1/16W; .Checked PCB: used; Temperature Coefficient: ±100ppm/°C
R294 R295 = RC0805JR-070RL_small: RES 0.0 OHM 1/8W 0805 SMD; Manufacturer: Yageo; Resistance (Ohms): 0.0; Power (Watts): 0.125W, 1/8W; Tolerance: Jumper; .Checked PCB: MM
R358 = RC0402FR-071ML: RES 1.00M OHM 1/16W 1% 0402 SMD; Manufacturer: Yageo; Power (Watts): 0.063W, 1/16W; .Checked PCB: used; Temperature Coefficient: ±100ppm/°C
TP4 = TP_25MILC: Test Point 25mil
U13 = USB2514BI-AEZG: USB HUB CONT IND TEMP 36QFNE3; Manufacturer: Microchip Technology; Function: Hub Controller; Standards: USB 2.0; Voltage - Supply: 3 V ~ 3.6 V; Current - Supply: 85mA; .Creator: MM; .Checked PCB: used
U17 = MIC2026-1YM TR: IC SW DISTRIBUTION 2CHAN 8SOIC; Manufacturer: Micrel Inc; .Checked PCB: used; Number of Outputs: 2; Rds (On): 140 mOhm; Internal Switch(s): Yes; Current Limit: 900mA; Voltage - Input: 2.7 V ~ 5.5 V
Y4 = ABM8-24.000MHZ-R60-D-1-W-T: CRYSTAL 24MHZ 18PF SMD; Manufacturer: Abracon Corporation; Frequency Stability: ±25ppm; Frequency Tolerance: ±10ppm; ESR (Equivalent Series Resistance): 50 Ohm; Operating Mode: Fundamental; .Creator: MM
